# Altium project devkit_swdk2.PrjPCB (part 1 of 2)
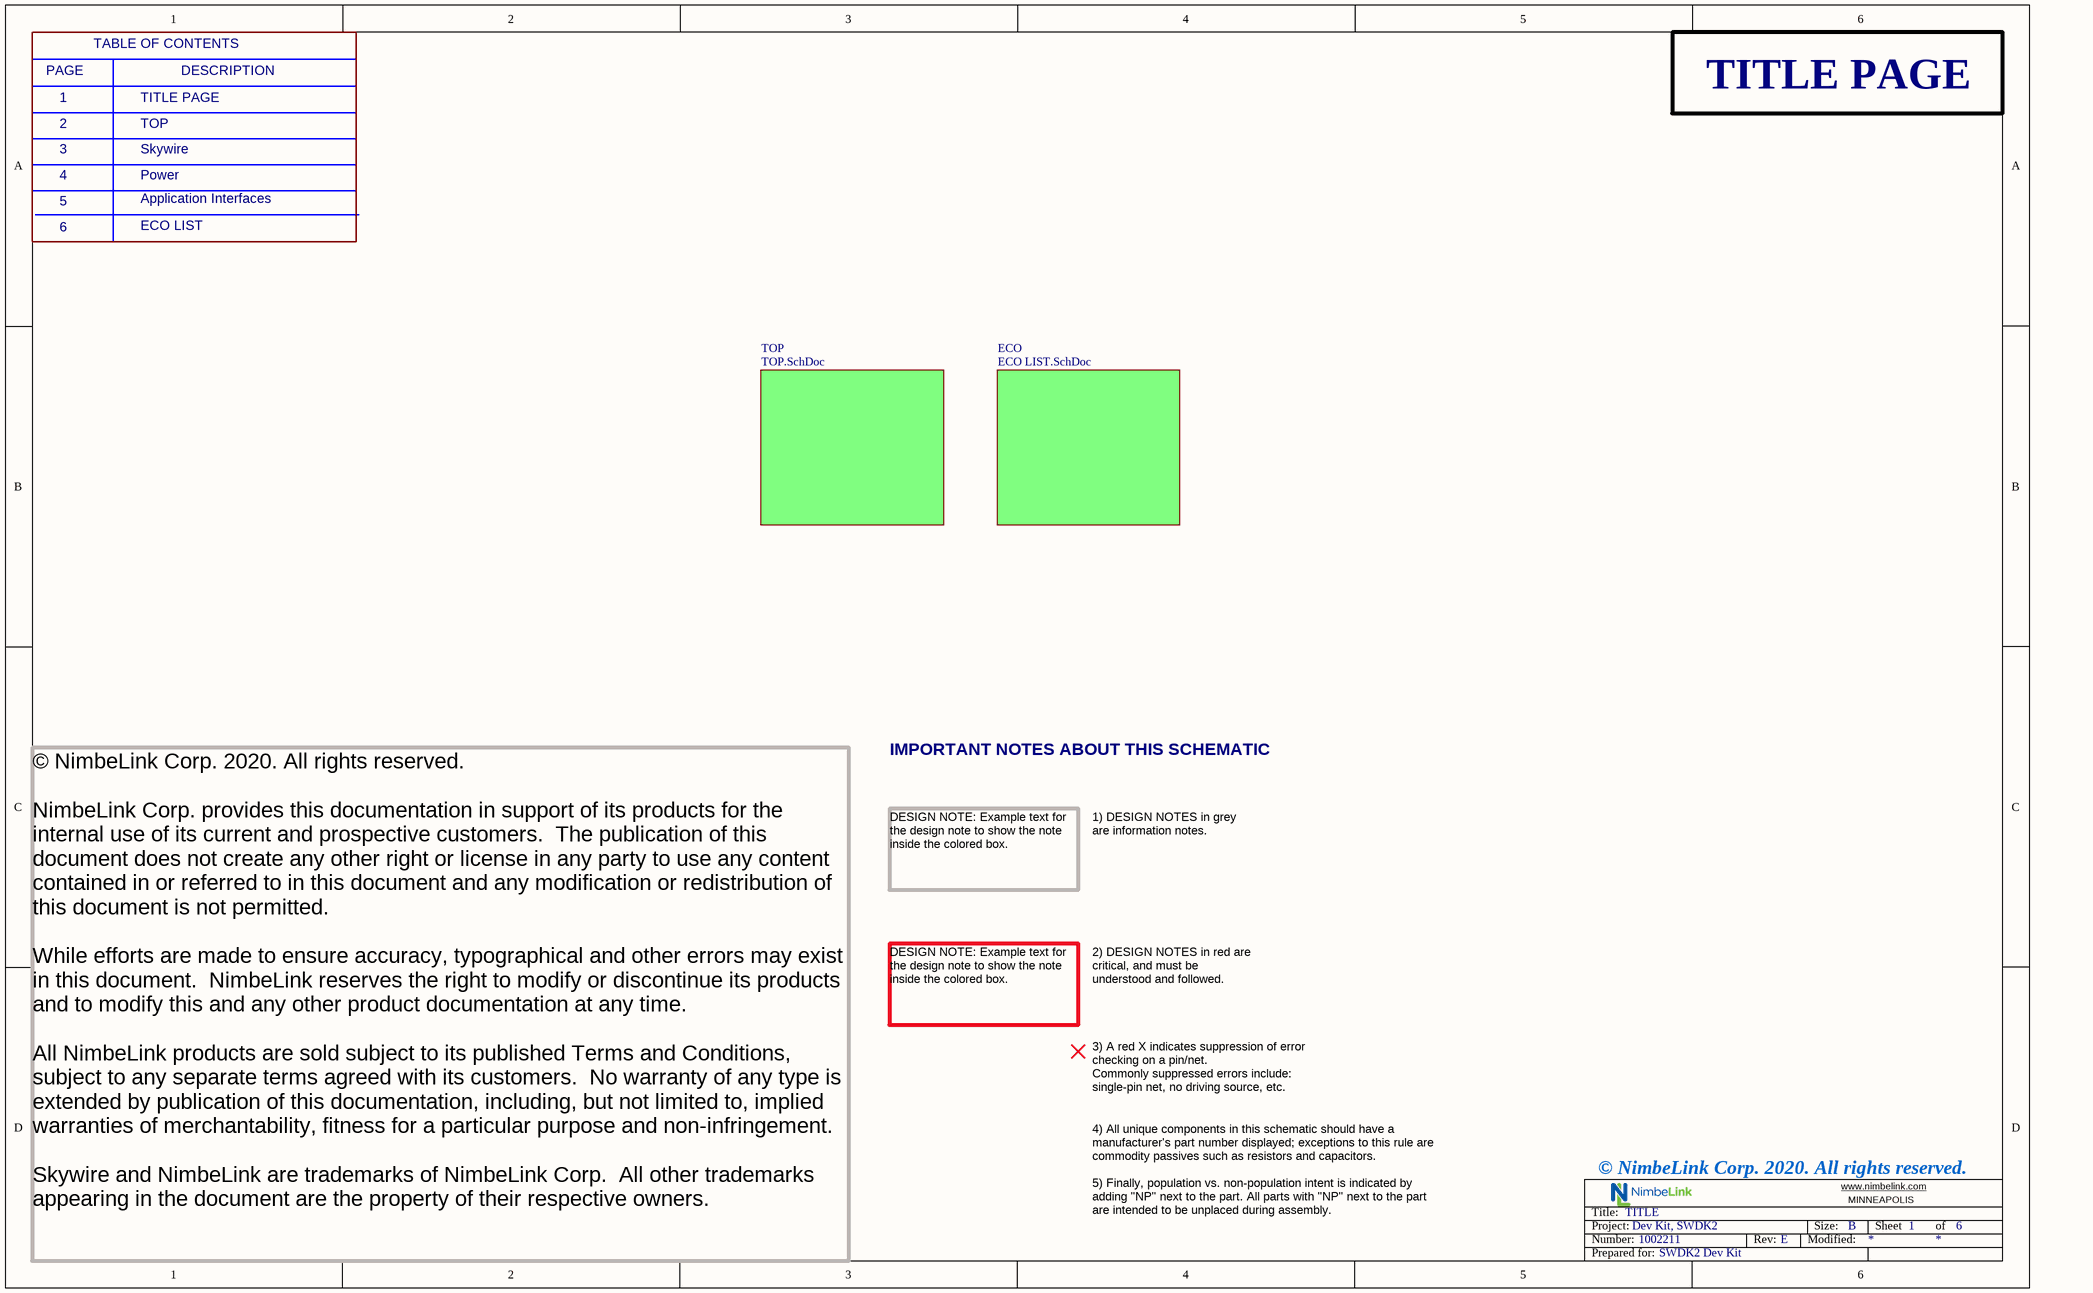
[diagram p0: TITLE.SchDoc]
NL_BILLING_CODE: Dev Kit, SWDK2; NL_PCB_PN: 1003008; NL_PCB_REV: A; NL_PCBA_PN: 1002213; NL_PCBA_REV: J; NL_SCH_PN: 1002211; NL_SCH_REV: E; NL_VERBOSE_CUST_NAME: SWDK2 Dev Kit; ProjectOrganization: Nimbelink, Corp; ProjectTitle: SWDK2 Dev Kit
6 sheets, 225 parts. Net scope: flat (ports and power ports of the same name join across sheets).
Board file: devkit_swdk2.PcbDoc
Sheets:
  TITLE.SchDoc
    TOP = TOP.SchDoc
      Power = Power.SchDoc
      Skywire = Skywire.SchDoc
      Application Interfaces = Application Interfaces.SchDoc
    ECO = ECO LIST.SchDoc

## Sheet TITLE.SchDoc: TITLE
size B; DocumentNumber: 1; SheetNumber: 1; SheetTotal: 6

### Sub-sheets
ECO = ECO LIST.SchDoc: no entries
TOP = TOP.SchDoc: no entries

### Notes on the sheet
- PAGE
- 1
- TABLE OF CONTENTS
- TITLE PAGE
- DESCRIPTION
- 2
- 3
- TOP
- Skywire
- 4
- 5
- 6
- Power
- ECO LIST
- Application Interfaces
- IMPORTANT NOTES ABOUT THIS SCHEMATIC
- DESIGN NOTE: Example text for the design note to show the note inside the colored box.
- 1) DESIGN NOTES in grey are information notes.
- 2) DESIGN NOTES in red are critical, and must be understood and followed.
- 3) A red X indicates suppression of error checking on a pin/net.
  Commonly suppressed errors include: single-pin net, no driving source, etc.
- © NimbeLink Corp. 2020. All rights reserved.
- 4) All unique components in this schematic should have a manufacturer's part number displayed; exceptions to this rule are commodity passives such as resistors and capacitors.
  5) Finally, population vs. non-population intent is indicated by adding "NP" next to the part. All parts with "NP" next to the part are intended to be unplaced during assembly.
- © NimbeLink Corp. 2020. All rights reserved.
  NimbeLink Corp. provides this documentation in support of its products for the internal use of its current and prospective customers.  The publication of this document does not create any other right or license in any party to use any content contained in or referred to in this document and any modification or redistribution of this document is not permitted.
  While efforts are made to ensure accuracy, typographical and other errors may exist in this document.  NimbeLink reserves the right to modify or discontinue its products and to modify this and any other product documentation at any time.
  All NimbeLink products are sold subject to its published Terms and Conditions, subject to any separate terms agreed with its customers.  No warranty of any type is extended by publication of this documentation, including, but not limited to, implied warranties of merchantability, fitness for a particular purpose and non-infringement.
  Skywire and NimbeLink are trademarks of NimbeLink Corp.  All other trademarks appearing in the document are the property of their respective owners.

## Sheet TOP.SchDoc: TOP
size C; DocumentNumber: 2; SheetNumber: 2; SheetTotal: 6
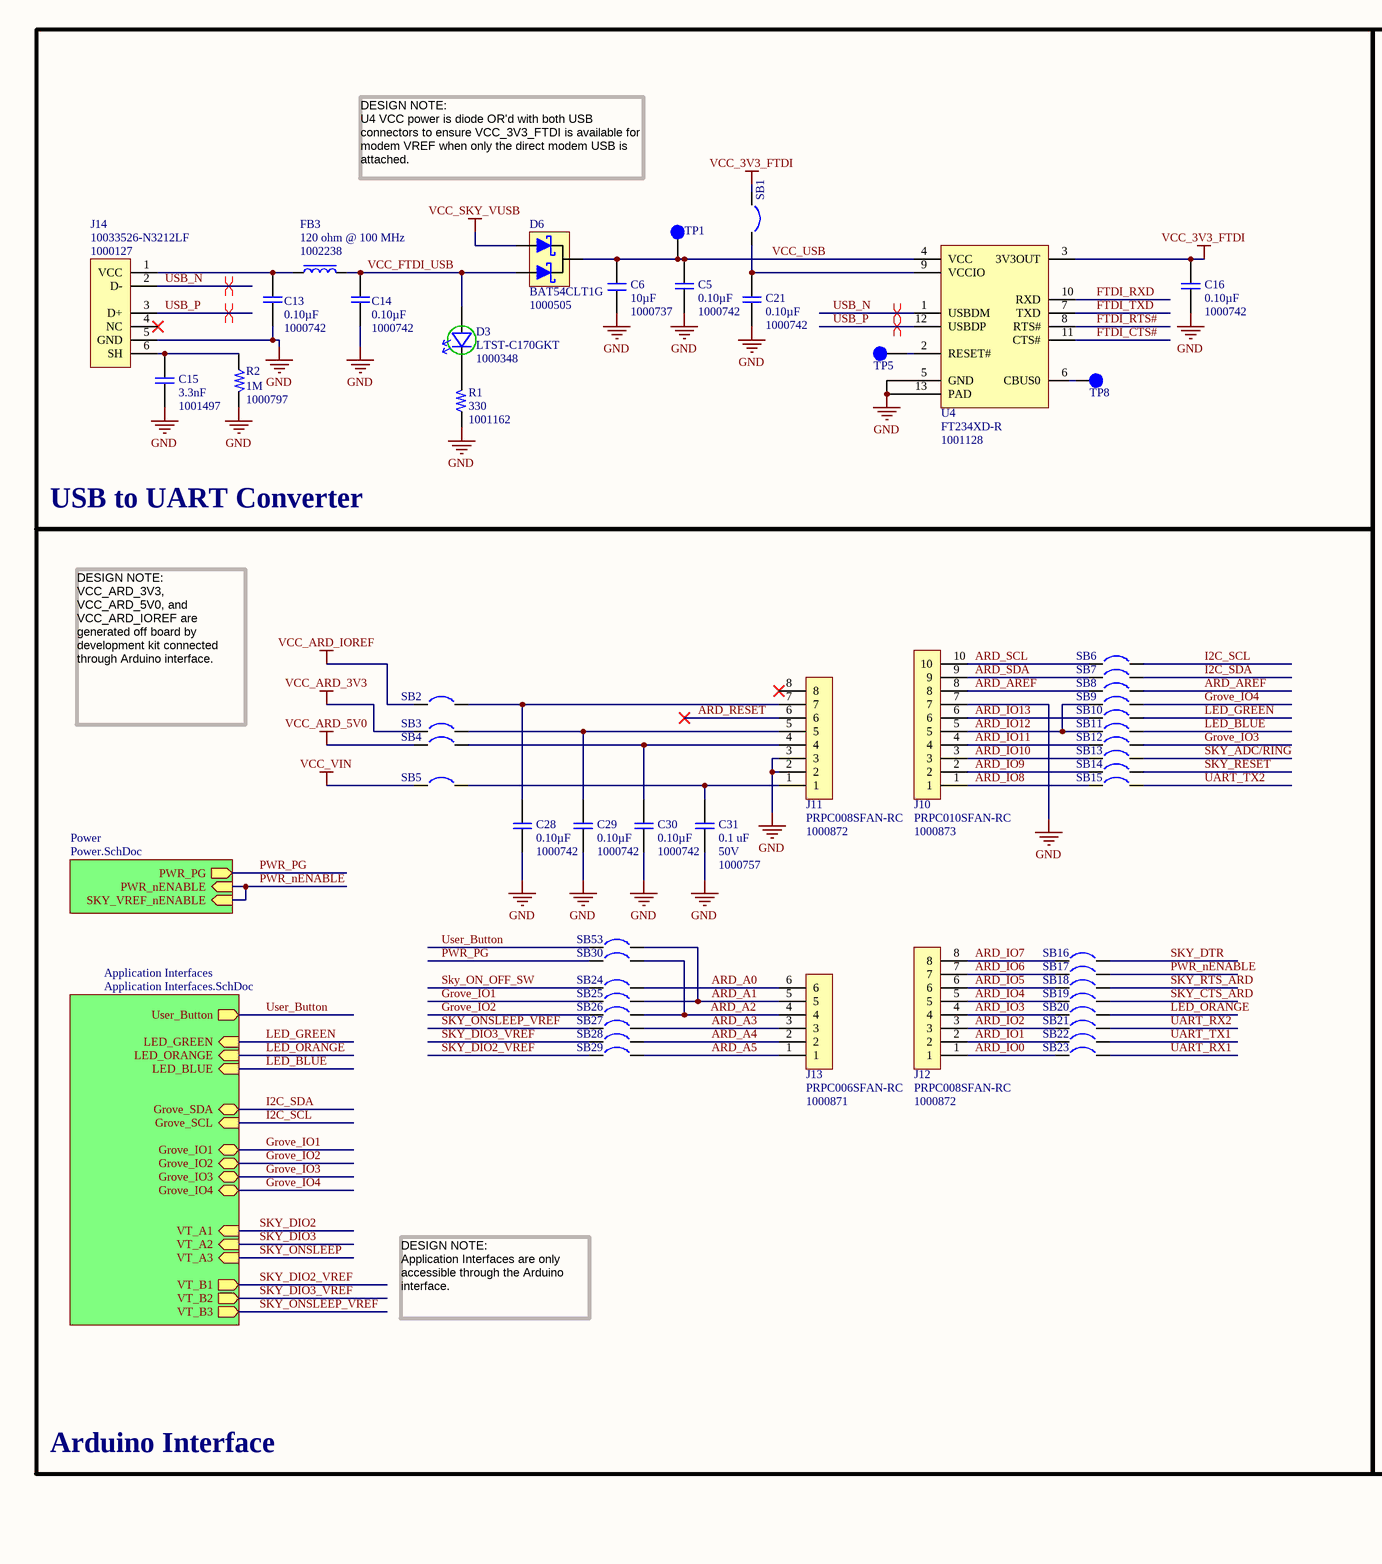
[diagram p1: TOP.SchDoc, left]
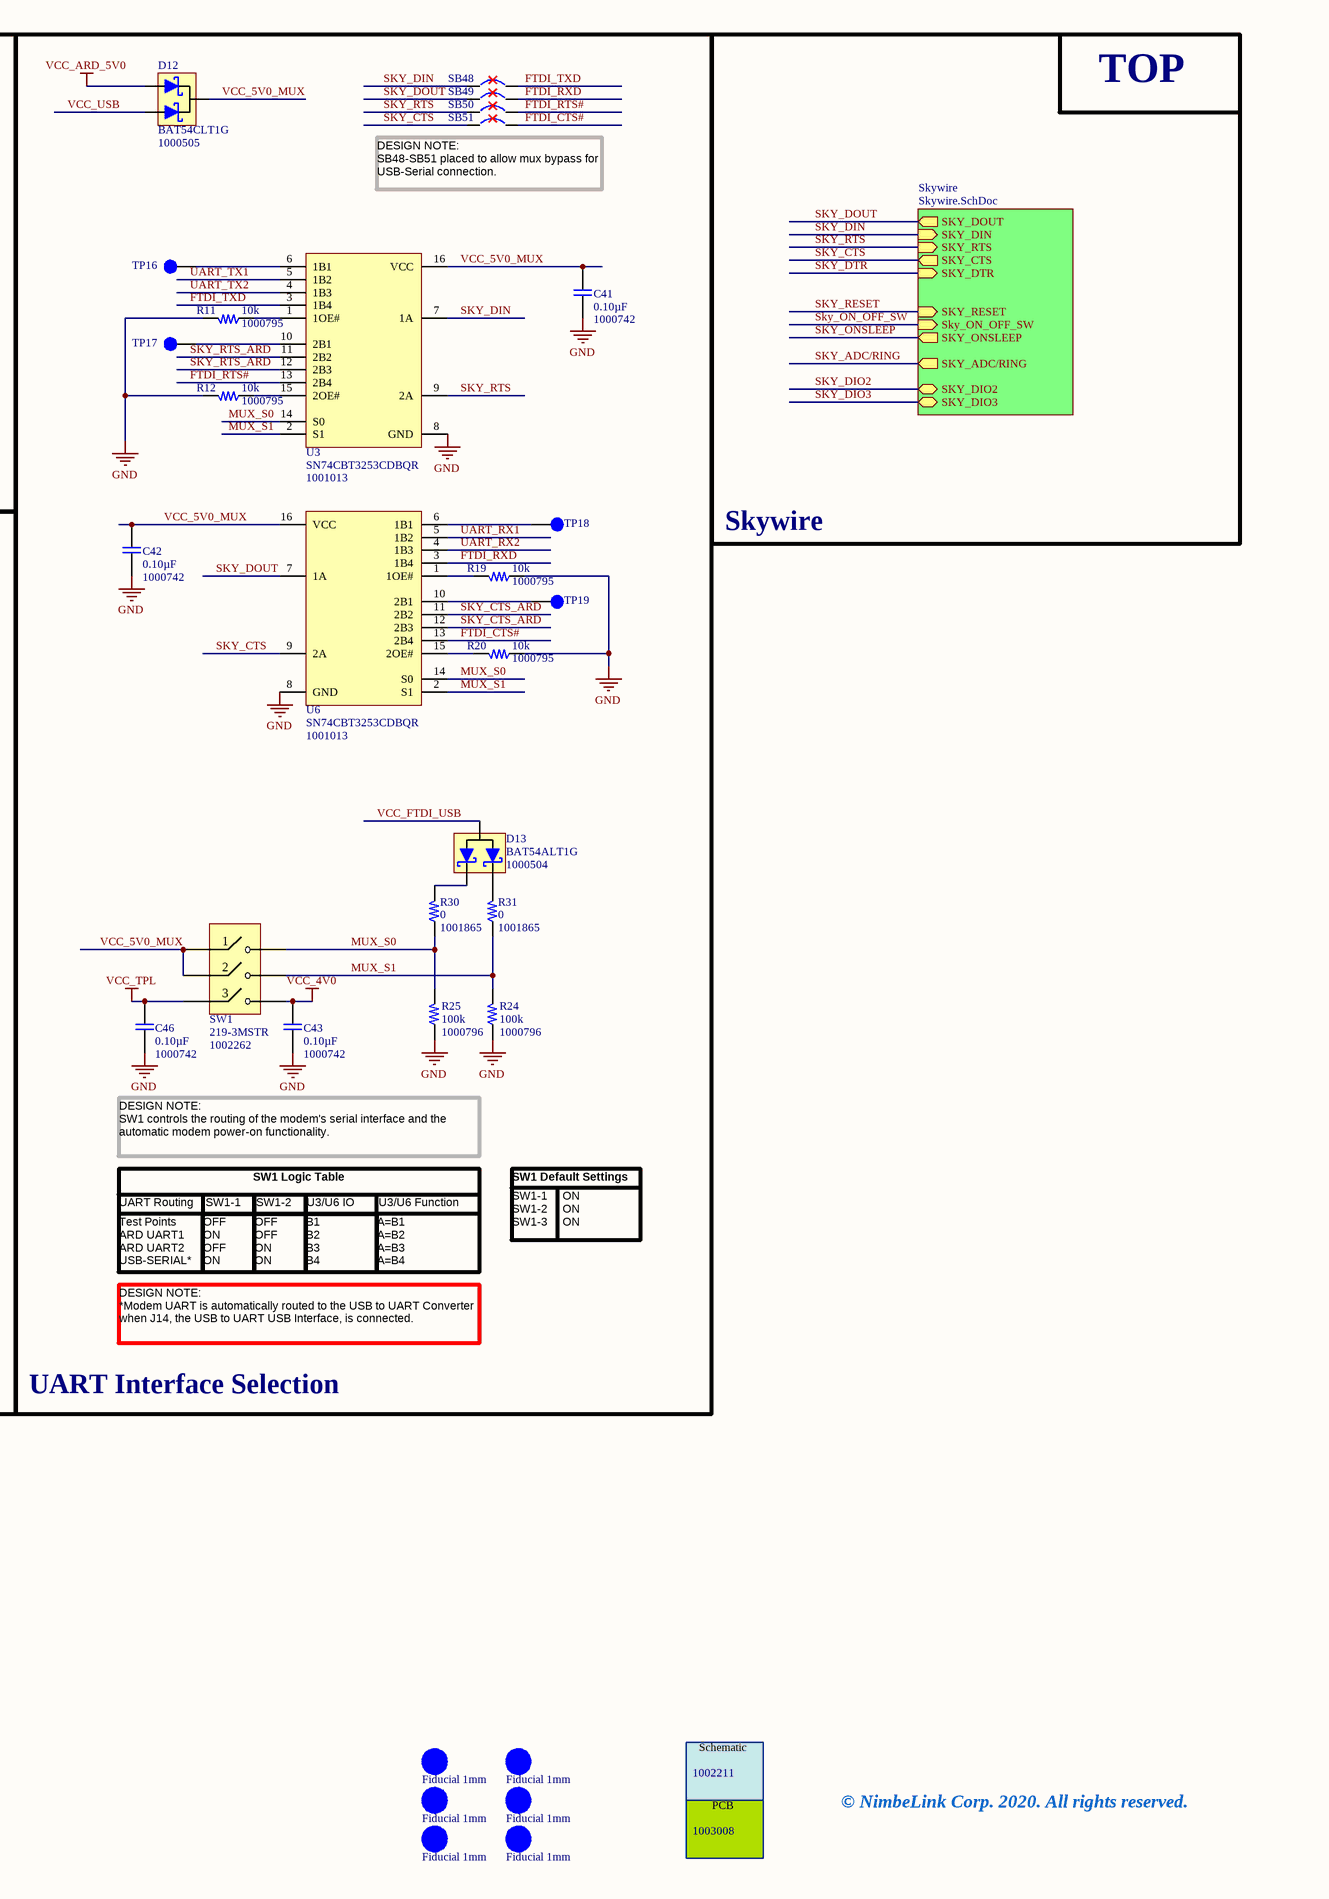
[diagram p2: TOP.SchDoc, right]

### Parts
C5  Capacitance: 0.10µF  Part_Number: 1000742  [0402]
C6  Part_Number: 1000737  Capacitance: 10µF  [0402 +-0.2mm Width]  (hidden comment: C, 10 uF, 10V, X5R, 20%, 0402 CER)
C13  Capacitance: 0.10µF  Part_Number: 1000742  [0402]
C14  Capacitance: 0.10µF  Part_Number: 1000742  [0402]
C15  Part_Number: 1001497  Capacitance: 3.3nF  [0402]  (hidden comment: CAPACITOR)
C16  Capacitance: 0.10µF  Part_Number: 1000742  [0402]
C21  Capacitance: 0.10µF  Part_Number: 1000742  [0402]
C28  Capacitance: 0.10µF  Part_Number: 1000742  [0402]
C29  Capacitance: 0.10µF  Part_Number: 1000742  [0402]
C30  Capacitance: 0.10µF  Part_Number: 1000742  [0402]
C31  Part_Number: 1000757  Capacitance: 0.1 uF  Voltage_Rating: 50V  [0603]  (hidden comment: CAPACITOR)
C41  Capacitance: 0.10µF  Part_Number: 1000742  [0402]
C42  Capacitance: 0.10µF  Part_Number: 1000742  [0402]
C43  Capacitance: 0.10µF  Part_Number: 1000742  [0402]
C46  Capacitance: 0.10µF  Part_Number: 1000742  [0402]
D3  Part_Number: 1000348  [D_LED_GREEN]  (hidden comment: LTST-C170GKT)
D6  Part_Number: 1000505  [SOT23-STYLE9]  (hidden comment: BAT54CLT1G)
D12  Part_Number: 1000505  [SOT23-STYLE9]  (hidden comment: BAT54CLT1G)
D13  Part_Number: 1000504  [SOT23-STYLE9]  (hidden comment: BAT54ALT1G)
FB3  Part_Number: 1002238  Resistance_at_Frequency: 120 ohm @ 100 MHz  [0603]  (hidden comment: FERRITE)
Fiducial1  Fiducial 1mm  [Fiducial 1mm]  (no BOM)
Fiducial2  Fiducial 1mm  [Fiducial 1mm]  (no BOM)
Fiducial3  Fiducial 1mm  [Fiducial 1mm]  (no BOM)
Fiducial4  Fiducial 1mm  [Fiducial 1mm]  (no BOM)
Fiducial5  Fiducial 1mm  [Fiducial 1mm]  (no BOM)
Fiducial6  Fiducial 1mm  [Fiducial 1mm]  (no BOM)
J10  Part_Number: 1000873  [PRPC010SFAN-RC]  (hidden comment: PRPC010SFAN-RC)
J11  Part_Number: 1000872  [PRPC008SFAN-RC]  (hidden comment: PRPC008SFAN-RC)
J12  Part_Number: 1000872  [PRPC008SFAN-RC]  (hidden comment: PRPC008SFAN-RC)
J13  Part_Number: 1000871  [PRPC006SFAN-RC]  (hidden comment: PRPC006SFAN-RC)
J14  Part_Number: 1000127  [10033526-N3212LF]  (hidden comment: USB MINI B)
PCB1  Part_Number: 1003008  (hidden comment: PCB)  (mechanical)
R1  Part_Number: 1001162  Resistance_Ohms: 330  [0402]  (hidden comment: R, 330, 1%, 1/10W, 0402)
R2  Part_Number: 1000797  Resistance_Ohms: 1M  [0402]  (hidden comment: R, 1M, 1%, 1/16W, 0402)
R11  Part_Number: 1000795  Resistance_Ohms: 10k  [0402]  (hidden comment: R, 10K, 1%, 1/16W,  0402)
R12  Part_Number: 1000795  Resistance_Ohms: 10k  [0402]  (hidden comment: R, 10K, 1%, 1/16W,  0402)
R19  Part_Number: 1000795  Resistance_Ohms: 10k  [0402]  (hidden comment: R, 10K, 1%, 1/16W,  0402)
R20  Part_Number: 1000795  Resistance_Ohms: 10k  [0402]  (hidden comment: R, 10K, 1%, 1/16W,  0402)
R24  Part_Number: 1000796  Resistance_Ohms: 100k  [0402]  (hidden comment: R, 100K, 1%, 1/16W,  0402)
R25  Part_Number: 1000796  Resistance_Ohms: 100k  [0402]  (hidden comment: R, 100K, 1%, 1/16W,  0402)
R30  Resistance_Ohms: 0  Part_Number: 1001865  [0402]  (hidden comment: RESISTOR)
R31  Resistance_Ohms: 0  Part_Number: 1001865  [0402]  (hidden comment: RESISTOR)
SB1  Solder Bridge  [Solder Bridge 0603 Closed]  (value not drawn)
SB2  Solder Bridge  [Solder Bridge 0603 Closed]  (value not drawn)
SB3  Solder Bridge  [Solder Bridge 0603 Closed]  (value not drawn)
SB4  Solder Bridge  [Solder Bridge 0603 Closed]  (value not drawn)
SB5  Solder Bridge  [Solder Bridge 0603 Closed]  (value not drawn)
SB6  Solder Bridge  [Solder Bridge 0603 Closed]  (value not drawn)
SB7  Solder Bridge  [Solder Bridge 0603 Closed]  (value not drawn)
SB8  Solder Bridge  [Solder Bridge 0603 Closed]  (value not drawn)
SB9  Solder Bridge  [Solder Bridge 0603 Closed]  (value not drawn)
SB10  Solder Bridge  [Solder Bridge 0603 Closed]  (value not drawn)
SB11  Solder Bridge  [Solder Bridge 0603 Closed]  (value not drawn)
SB12  Solder Bridge  [Solder Bridge 0603 Closed]  (value not drawn)
SB13  Solder Bridge  [Solder Bridge 0603 Closed]  (value not drawn)
SB14  Solder Bridge  [Solder Bridge 0603 Closed]  (value not drawn)
SB15  Solder Bridge  [Solder Bridge 0603 Closed]  (value not drawn)
SB16  Solder Bridge  [Solder Bridge 0603 Closed]  (value not drawn)
SB17  Solder Bridge  [Solder Bridge 0603 Closed]  (value not drawn)
SB18  Solder Bridge  [Solder Bridge 0603 Closed]  (value not drawn)
SB19  Solder Bridge  [Solder Bridge 0603 Closed]  (value not drawn)
SB20  Solder Bridge  [Solder Bridge 0603 Closed]  (value not drawn)
SB21  Solder Bridge  [Solder Bridge 0603 Closed]  (value not drawn)
SB22  Solder Bridge  [Solder Bridge 0603 Closed]  (value not drawn)
SB23  Solder Bridge  [Solder Bridge 0603 Closed]  (value not drawn)
SB24  Solder Bridge  [Solder Bridge 0603 Closed]  (value not drawn)
SB25  Solder Bridge  [Solder Bridge 0603 Closed]  (value not drawn)
SB26  Solder Bridge  [Solder Bridge 0603 Closed]  (value not drawn)
SB27  Solder Bridge  [Solder Bridge 0603 Closed]  (value not drawn)
SB28  Solder Bridge  [Solder Bridge 0603 Closed]  (value not drawn)
SB29  Solder Bridge  [Solder Bridge 0603 Closed]  (value not drawn)
SB30  Solder Bridge  [Solder Bridge 0603 Closed]  (value not drawn)
SB48  Solder Bridge  [SOLDER BRIDGE 0603]  (value not drawn)  (no BOM)
SB49  Solder Bridge  [SOLDER BRIDGE 0603]  (value not drawn)  (no BOM)
SB50  Solder Bridge  [SOLDER BRIDGE 0603]  (value not drawn)  (no BOM)
SB51  Solder Bridge  [SOLDER BRIDGE 0603]  (value not drawn)  (no BOM)
SB53  Solder Bridge  [Solder Bridge 0603 Closed]  (value not drawn)
SCH1  Part_Number: 1002211  (hidden comment: SCH)  (mechanical)
SW1  Part_Number: 1002262  [219-3MSTR]  (hidden comment: DIP-3pin)
TP1  Test Point 1mm  [Test_Point 1mm]  (value not drawn)  (no BOM)
TP5  Test Point 1mm  [Test_Point 1mm]  (value not drawn)  (no BOM)
TP8  Test Point 1mm  [Test_Point 1mm]  (value not drawn)  (no BOM)
TP16  Test Point 1mm  [Test_Point 1mm]  (value not drawn)  (no BOM)
TP17  Test Point 1mm  [Test_Point 1mm]  (value not drawn)  (no BOM)
TP18  Test Point 1mm  [Test_Point 1mm]  (value not drawn)  (no BOM)
TP19  Test Point 1mm  [Test_Point 1mm]  (value not drawn)  (no BOM)
U3  Part_Number: 1001013  [SN74CBT3253CDBQR]  (hidden comment: SN74CBT3253CDBQR)
U4  Manufacturer_Part_Number1: FT234XD-R  Part_Number: 1001128  [QFN45P300X300X80_HS-13N]  (hidden comment: FT234XD)
U6  Part_Number: 1001013  [SN74CBT3253CDBQR]  (hidden comment: SN74CBT3253CDBQR)

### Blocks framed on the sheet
USB to UART Converter: C5 C6 C13-C16 C21 D3 D6 FB3 J14 R1 R2 SB1 TP1 TP5 TP8 U4
UART Interface Selection: C41-C43 C46 D12 D13 R11 R12 R19 R20 R24 R25 R30 R31 SB48-SB51 SW1 TP16-TP19 U3 U6
Arduino Interface: C28-C31 J10-J13 SB2-SB30 SB53

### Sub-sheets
Application Interfaces = Application Interfaces.SchDoc: Grove_IO1 (bidir), Grove_SDA (bidir), User_Button (out), Grove_IO4 (bidir), Grove_IO2 (bidir), LED_GREEN (in), LED_ORANGE (in), Grove_IO3 (bidir), LED_BLUE (in), Grove_SCL (in), VT_A1 (in), VT_A2 (in), VT_A3 (in), VT_B1 (out), VT_B2 (out), VT_B3 (out)
Power = Power.SchDoc: PWR_PG (out), PWR_nENABLE (in), SKY_VREF_nENABLE (in)
Skywire = Skywire.SchDoc: SKY_RESET (in), SKY_CTS (out), SKY_DOUT (out), SKY_DIN (in), Sky_ON_OFF_SW (in), SKY_RTS (in), SKY_DTR (in), SKY_ONSLEEP (out), SKY_DIO2 (bidir), SKY_DIO3 (bidir), SKY_ADC/RING (out)

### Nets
GND: C5.2 C6.2 C13.2 C14.2 C15.1 C16.2 C21.2 C28.2 C29.2 C30.2 C31.2 C41.2 C42.2 C43.2 C46.2 J10.7 J11.2 J11.3 J14.5(GND) R1.1 R2.1 R11.2 R12.2 R19.1 R20.1 R24.1 R25.1 U3.8(GND) U4.5(GND) U4.13(PAD) U6.8(GND)
VCC_3V3_FTDI: C16.1 SB1.1 U4.3(3V3OUT)
VCC_4V0: C43.1 SW1.4
VCC_ARD_3V3: SB3.1
VCC_ARD_5V0: D12.2 SB4.1
VCC_ARD_IOREF: SB2.1
VCC_SKY_VUSB: D6.2
VCC_TPL: C46.1 SW1.3
VCC_VIN: SB5.1
ARD_A0: J13.6 SB24.2
ARD_A1: J13.5 SB25.2 SB53.2
ARD_A2: J13.4 SB26.2 SB30.2
ARD_A3: J13.3 SB27.2
ARD_A4: J13.2 SB28.2
ARD_A5: J13.1 SB29.2
ARD_AREF: J10.8 SB8.1 SB8.2
ARD_IO0: J12.1 SB23.1
ARD_IO1: J12.2 SB22.1
ARD_IO2: J12.3 SB21.1
ARD_IO3: J12.4 SB20.1
ARD_IO4: J12.5 SB19.1
ARD_IO5: J12.6 SB18.1
ARD_IO6: J12.7 SB17.1
ARD_IO7: J12.8 SB16.1
ARD_IO8: J10.1 SB15.1
ARD_IO9: J10.2 SB14.1
ARD_IO10: J10.3 SB13.1
ARD_IO11: J10.4 SB12.1
ARD_IO12: J10.5 SB9.1 SB11.1
ARD_IO13: J10.6 SB10.1
ARD_RESET: J11.6
ARD_SCL: J10.10 SB6.1
ARD_SDA: J10.9 SB7.1
FTDI_CTS#: SB51.2 U4.11(CTS#) U6.13(2B4)
FTDI_RTS#: SB50.2 U3.13(2B4) U4.8(RTS#)
FTDI_RXD: SB49.2 U4.10(RXD) U6.3(1B4)
FTDI_TXD: SB48.2 U3.3(1B4) U4.7(TXD)
Grove_IO1: SB25.1 ; sheet Application Interfaces/Grove_IO1
Grove_IO2: SB26.1 ; sheet Application Interfaces/Grove_IO2
Grove_IO3: SB12.2 ; sheet Application Interfaces/Grove_IO3
Grove_IO4: SB9.2 ; sheet Application Interfaces/Grove_IO4
I2C_SCL: SB6.2 ; sheet Application Interfaces/Grove_SCL
I2C_SDA: SB7.2 ; sheet Application Interfaces/Grove_SDA
LED_BLUE: SB11.2 ; sheet Application Interfaces/LED_BLUE
LED_GREEN: SB10.2 ; sheet Application Interfaces/LED_GREEN
LED_ORANGE: SB20.2 ; sheet Application Interfaces/LED_ORANGE
MUX_S0: R25.2 R30.1 SW1.6 U3.14(S0) U6.14(S0)
MUX_S1: R24.2 R31.1 SW1.5 U3.2(S1) U6.2(S1)
PWR_nENABLE: SB17.2 ; sheet Power/PWR_nENABLE, sheet Power/SKY_VREF_nENABLE
PWR_PG: SB30.1 ; sheet Power/PWR_PG
SKY_ADC/RING: SB13.2 ; sheet Skywire/SKY_ADC/RING
SKY_CTS: SB51.1 U6.9(2A) ; sheet Skywire/SKY_CTS
SKY_CTS_ARD: SB19.2 U6.11(2B2) U6.12(2B3)
SKY_DIN: SB48.1 U3.7(1A) ; sheet Skywire/SKY_DIN
SKY_DIO2: sheet Skywire/SKY_DIO2, sheet Application Interfaces/VT_A1
SKY_DIO2_VREF: SB29.1 ; sheet Application Interfaces/VT_B1
SKY_DIO3: sheet Skywire/SKY_DIO3, sheet Application Interfaces/VT_A2
SKY_DIO3_VREF: SB28.1 ; sheet Application Interfaces/VT_B2
SKY_DOUT: SB49.1 U6.7(1A) ; sheet Skywire/SKY_DOUT
SKY_DTR: SB16.2 ; sheet Skywire/SKY_DTR
Sky_ON_OFF_SW: SB24.1 ; sheet Skywire/Sky_ON_OFF_SW
SKY_ONSLEEP: sheet Skywire/SKY_ONSLEEP, sheet Application Interfaces/VT_A3
SKY_ONSLEEP_VREF: SB27.1 ; sheet Application Interfaces/VT_B3
SKY_RESET: SB14.2 ; sheet Skywire/SKY_RESET
SKY_RTS: SB50.1 U3.9(2A) ; sheet Skywire/SKY_RTS
SKY_RTS_ARD: SB18.2 U3.11(2B2) U3.12(2B3)
UART_RX1: SB23.2 U6.5(1B2)
UART_RX2: SB21.2 U6.4(1B3)
UART_TX1: SB22.2 U3.5(1B2)
UART_TX2: SB15.2 U3.4(1B3)
USB_N: J14.2(D-) U4.1(USBDM)
USB_P: J14.3(D+) U4.12(USBDP)
User_Button: SB53.1 ; sheet Application Interfaces/User_Button
VCC_5V0_MUX: C41.1 C42.1 D12.3 SW1.1 SW1.2 U3.16(VCC) U6.16(VCC)
VCC_FTDI_USB: C14.1 D3.1(Anode) D6.1 D13.3 FB3.2
VCC_USB: C5.1 C6.1 D6.3 D12.1 TP1.1 U4.4(VCC)
NetC13_1: C13.1 FB3.1 J14.1(VCC)
NetC15_2: C15.2 J14.6(SH) R2.2
NetC21_1: C21.1 SB1.2 U4.9(VCCIO)
NetC28_1: C28.1 J11.7 SB2.2
NetC29_1: C29.1 J11.5 SB3.2
NetC30_1: C30.1 J11.4 SB4.2
NetC31_1: C31.1 J11.1 SB5.2
NetD3_2: D3.2(Cathode) R1.2
NetD13_1: D13.1 R30.2
NetD13_2: D13.2 R31.2
NetR11_1: R11.1 U3.1(1OE#)
NetR12_1: R12.1 U3.15(2OE#)
NetR19_2: R19.2 U6.1(1OE#)
NetR20_2: R20.2 U6.15(2OE#)
NetTP5_1: TP5.1 U4.2(RESET#)
NetTP8_1: TP8.1 U4.6(CBUS0)
NetTP16_1: TP16.1 U3.6(1B1)
NetTP17_1: TP17.1 U3.10(2B1)
NetTP18_1: TP18.1 U6.6(1B1)
NetTP19_1: TP19.1 U6.10(2B1)

Not connected (* = marked no-connect by the designer): J11 8*; J14 4(NC)*

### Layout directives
differential pair: USB_N, USB_P

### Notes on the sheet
- TOP
- DESIGN NOTE:
  U4 VCC power is diode OR'd with both USB connectors to ensure VCC_3V3_FTDI is available for modem VREF when only the direct modem USB is attached.
- (near SB51) DESIGN NOTE:
  SB48-SB51 placed to allow mux bypass for USB-Serial connection.
- Skywire
- DESIGN NOTE:
  VCC_ARD_3V3, VCC_ARD_5V0, and VCC_ARD_IOREF are generated off board by development kit connected through Arduino interface.
- DESIGN NOTE:
  SW1 controls the routing of the modem's serial interface and the automatic modem power-on functionality.
- SW1 Default Settings
- SW1 Logic Table
- SW1-1     ON
  SW1-2     ON
  SW1-3     ON
- DESIGN NOTE:
  Application Interfaces are only accessible through the Arduino interface.
- UART Routing    SW1-1     SW1-2     U3/U6 IO        U3/U6 Function
- Test Points
  ARD UART1
  ARD UART2
  USB-SERIAL*
- OFF
  ON
  OFF
  ON
- OFF
  OFF
  ON
  ON
- B1
  B2
  B3
  B4
- A=B1
  A=B2
  A=B3
  A=B4
- DESIGN NOTE:
  *Modem UART is automatically routed to the USB to UART Converter when J14, the USB to UART USB Interface, is connected.
- © NimbeLink Corp. 2020. All rights reserved.

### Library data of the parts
C5 C13 C14 C16 C21 C28-C30 C41-C43 C46 = 1000742: Capacitor, 0.1 uF, 16V, 10%, X7R, 0402; Manufacturer1: Kemet; Manufacturer_Part_Number1: C0402C104K4RALTU; Item_Phase: Production; Capacitor_Type: Ceramic; Mounting_Type: Surface Mount; Operating_Temperature: -55°C ~ 125°C; Thickness_Max: 0.022" (0.55mm)
C6 = 1000737: Capacitor, 10 uF, 10V, 20%, X5R, 0402; Manufacturer1: Venkel LTD.; Manufacturer_Part_Number1: C0402X5R100-106MNP; Item_Phase: Production; Capacitor_Type: Ceramic; Mounting_Type: Surface Mount; Operating_Temperature: -55°C ~ 85°C; Thickness_Max: 0.035" (0.90mm)
C15 = 1001497: Capacitor, 3.3 nF, 50V, 10%, X7R, 0402; Manufacturer1: Murata; Manufacturer_Part_Number1: GRM155R71H332KA01D; Item_Phase: Production; Capacitor_Type: Ceramic; Mounting_Type: Surface Mount; Operating_Temperature: -55°C ~ 125°C; Thickness_Max: 0.022" (0.55mm)
C31 = 1000757: Capacitor, 0.1 uF, 50V, 10%, X7R, 0603; Manufacturer1: TDK Corporation; Manufacturer_Part_Number1: CGA3E2X7R1H104K080AA; Item_Phase: Production; Capacitor_Type: Ceramic; Mounting_Type: Surface Mount; Operating_Temperature: -55 to 125C
D3 = 1000348: Diode, LED, Green, 6mcd, 569nm, 0805; Manufacturer1: Lite-On Inc; Item_Phase: Production
D6 D12 = 1000505: Diode, Schottky, Dual, COM CATHODE, 30V, 0.35VF, 200MA, SOT23; Manufacturer1: ON Semiconductor; Item_Phase: Production; Current_Average_Rectified_IO: 200mA (DC); Current_Reverse_Leakage_at_Vref: 2µA @ 25V; Mounting_Type: Surface Mount; Voltage_Forward_VF_Max_at_I_Forward: 800mV @ 100mA
D13 = 1000504: Diode, Schottky, Dual, COM ANODE, 30V, 0.35 Vf, 200MA, SOT23; Manufacturer1: ON Semiconductor; Item_Phase: Production; Current_Average_Rectified_IO: 200mA (DC); Current_Reverse_Leakage_at_Vref: 2µA @ 25V; Mounting_Type: Surface Mount; Voltage_Forward_VF_Max_at_I_Forward: 800mV @ 100mA
FB3 = 1002238: Ferrite Bead, 120 ohm @100MHz, 3A, 30mOHM-DC, 0603; Manufacturer_Part_Number1: CIS10P121AC; Manufacturer1: Samsung Electro-Mechanics America, Inc; Item_Phase: Production; Mounting_Type: Surface Mount; Operating_Temperature: -55°C ~ 125°C; Resistance_DC: 30 mOhm
Fiducial1-Fiducial6 = Fiducial: Population: NP
J10 = 1000873: Connector, Header, Male, 2.54mm, 10x1, TH 8.08mm; Manufacturer1: Sullins Connector Solutions; Item_Phase: Production; Connector_Type: Header, Unshrouded, Breakaway; Contact_Finish: Gold; Contact_Type: Male Pin; Mounting_Type: Through Hole; Number_of_Positions: 10; Number_of_Positions_Loaded: All; Number_of_Rows: 1; Pitch: 0.100" (2.54mm)
J11 J12 = 1000872: Connector, Header, Male, 2.54mm, 8x1, TH, 8.08mm; Manufacturer1: Sullins Connector Solutions; Item_Phase: Production; Connector_Type: Header, Unshrouded, Breakaway; Contact_Finish: Gold; Contact_Type: Male Pin; Mounting_Type: Through Hole; Number_of_Positions: 8; Number_of_Positions_Loaded: All; Number_of_Rows: 1; Pitch: 0.100" (2.54mm)
J13 = 1000871: Connector, Header, Male, 2.54mm, 6x1, TH, 8.08mm; Manufacturer1: Sullins Connector Solutions; Item_Phase: Production; Connector_Type: Header, Unshrouded, Breakaway; Contact_Finish: Gold; Contact_Type: Male Pin; Mounting_Type: Through Hole; Number_of_Positions: 6; Number_of_Positions_Loaded: All; Number_of_Rows: 1; Pitch: 0.100" (2.54mm)
J14 = 1000127: Connector, USB, Mini B, Right Angle, SMD; Manufacturer1: Amphenol; Gender: Receptacle; Item_Phase: Production; Connector_Type: USB - mini B; Mounting_Type: Surface Mount Right Angle Horizontal; Number_of_Pins: 5
PCB1 = PCB: PCB Part Number
R1 = 1001162: Resistor, 330, 1%, 1/10W, 0402; Manufacturer1: Panasonic Electronic Components; Manufacturer_Part_Number1: ERJ-2RKF3300X; Item_Phase: Production; Mounting_Type: Surface Mount; Number_of_Terminations: 2; Operating_Temperature: -55°C ~ 155°C; Power: 0.1W, 1/10W; Resistor_Package: 0402 (1005 Metric); Temperature_Coefficient: ±100ppm/°C
R2 = 1000797: Resistor, 1M, 1%, 1/16W, 0402; Manufacturer1: Samsung Electro-Mechanics America, Inc; Manufacturer_Part_Number1: RC1005F105CS; Item_Phase: Production; Mounting_Type: Surface Mount; Number_of_Terminations: 2; Operating_Temperature: -55°C ~ 155°C; Power: 0.063W, 1/16W; Resistor_Package: 0402 (1005 Metric); Temperature_Coefficient: ±100ppm/°C
R11 R12 R19 R20 = 1000795: Resistor, 10K, 1%, 1/16W, 0402; Manufacturer1: Bourns Inc; Manufacturer_Part_Number1: CR0402-FX-1002GLF; Item_Phase: Production; Mounting_Type: Surface Mount; Number_of_Terminations: 2; Operating_Temperature: -55°C ~ 155°C; Power: 0.063W, 1/16W; Resistor_Package: 0402 (1005 Metric); Temperature_Coefficient: ±100ppm/°C
R24 R25 = 1000796: Resistor, 100K, 1%, 1/16W, 0402; Manufacturer1: Bourns Inc; Manufacturer_Part_Number1: CR0402-FX-1003GLF; Item_Phase: Production; Mounting_Type: Surface Mount; Number_of_Terminations: 2; Operating_Temperature: -55°C ~ 155°C; Power: 0.063W, 1/16W; Resistor_Package: 0402 (1005 Metric); Temperature_Coefficient: ±100ppm/°C
R30 R31 = 1001865: Resistor, 0, 1/16W, 0402; Manufacturer1: Bourns Inc; Manufacturer_Part_Number1: CR0402-J/-000GLF; Item_Phase: Production; Mounting_Type: Surface Mount; Number_of_Terminations: 2; Operating_Temperature: -55C ~ 155C; Resistor_Package: 0402 (1005 Metric)
SB1-SB30 SB53 = 1002269: Resistor, Solder Bridge, 0, 1/10W, 0603; Manufacturer_Part_Number1: ERJ-3GEY0R00V; Manufacturer1: Panasonic Electronic Components; Resistance_Ohms: 0; Item_Phase: Production; Mounting_Type: Surface Mount; Operating_Temperature: -55°C ~ 155°C; Resistor_Package: 0603 (1608 Metric)
SB48-SB51 = Solder Bridge, Open: Population: NP
SCH1 = SCH: Schematic Part Number
SW1 = 1002262: Switch, SPST, DIP 3, 20V, 0.1A, Washable, Raised Actuator, SMD; Manufacturer1: CTS; Item_Phase: Production; Actuator_Type: Slide; Mounting_Type: Surface Mount; Operating_Temperature: -55°C ~ 85°C
TP1 TP5 TP8 TP16-TP19 = TP_1mm: TEST POINT, SMD 1mm; Population: NP
U3 U6 = 1001013: IC, Multiplexer, Dual, 4:1, 4.5V-5.5V, SSOP-16; Manufacturer1: Texas Instruments; Item_Phase: Production; Mounting_Type: Surface Mount
U4 = 1001128: IC, Interface, UART-USB, 5V, DFN, 3x3mm; Manufacturer1: FTDI, Future Technology Devices International Ltd; Item_Phase: Production; Current_Supply: 8mA; Operating_Temperature: -40°C ~ 85°C; Voltage_Supply_Max: 5.5V; Voltage_Supply_Min: 2.97V

## Sheet Power.SchDoc: POWER
size B; DocumentNumber: 4; SheetNumber: 4; SheetTotal: 6
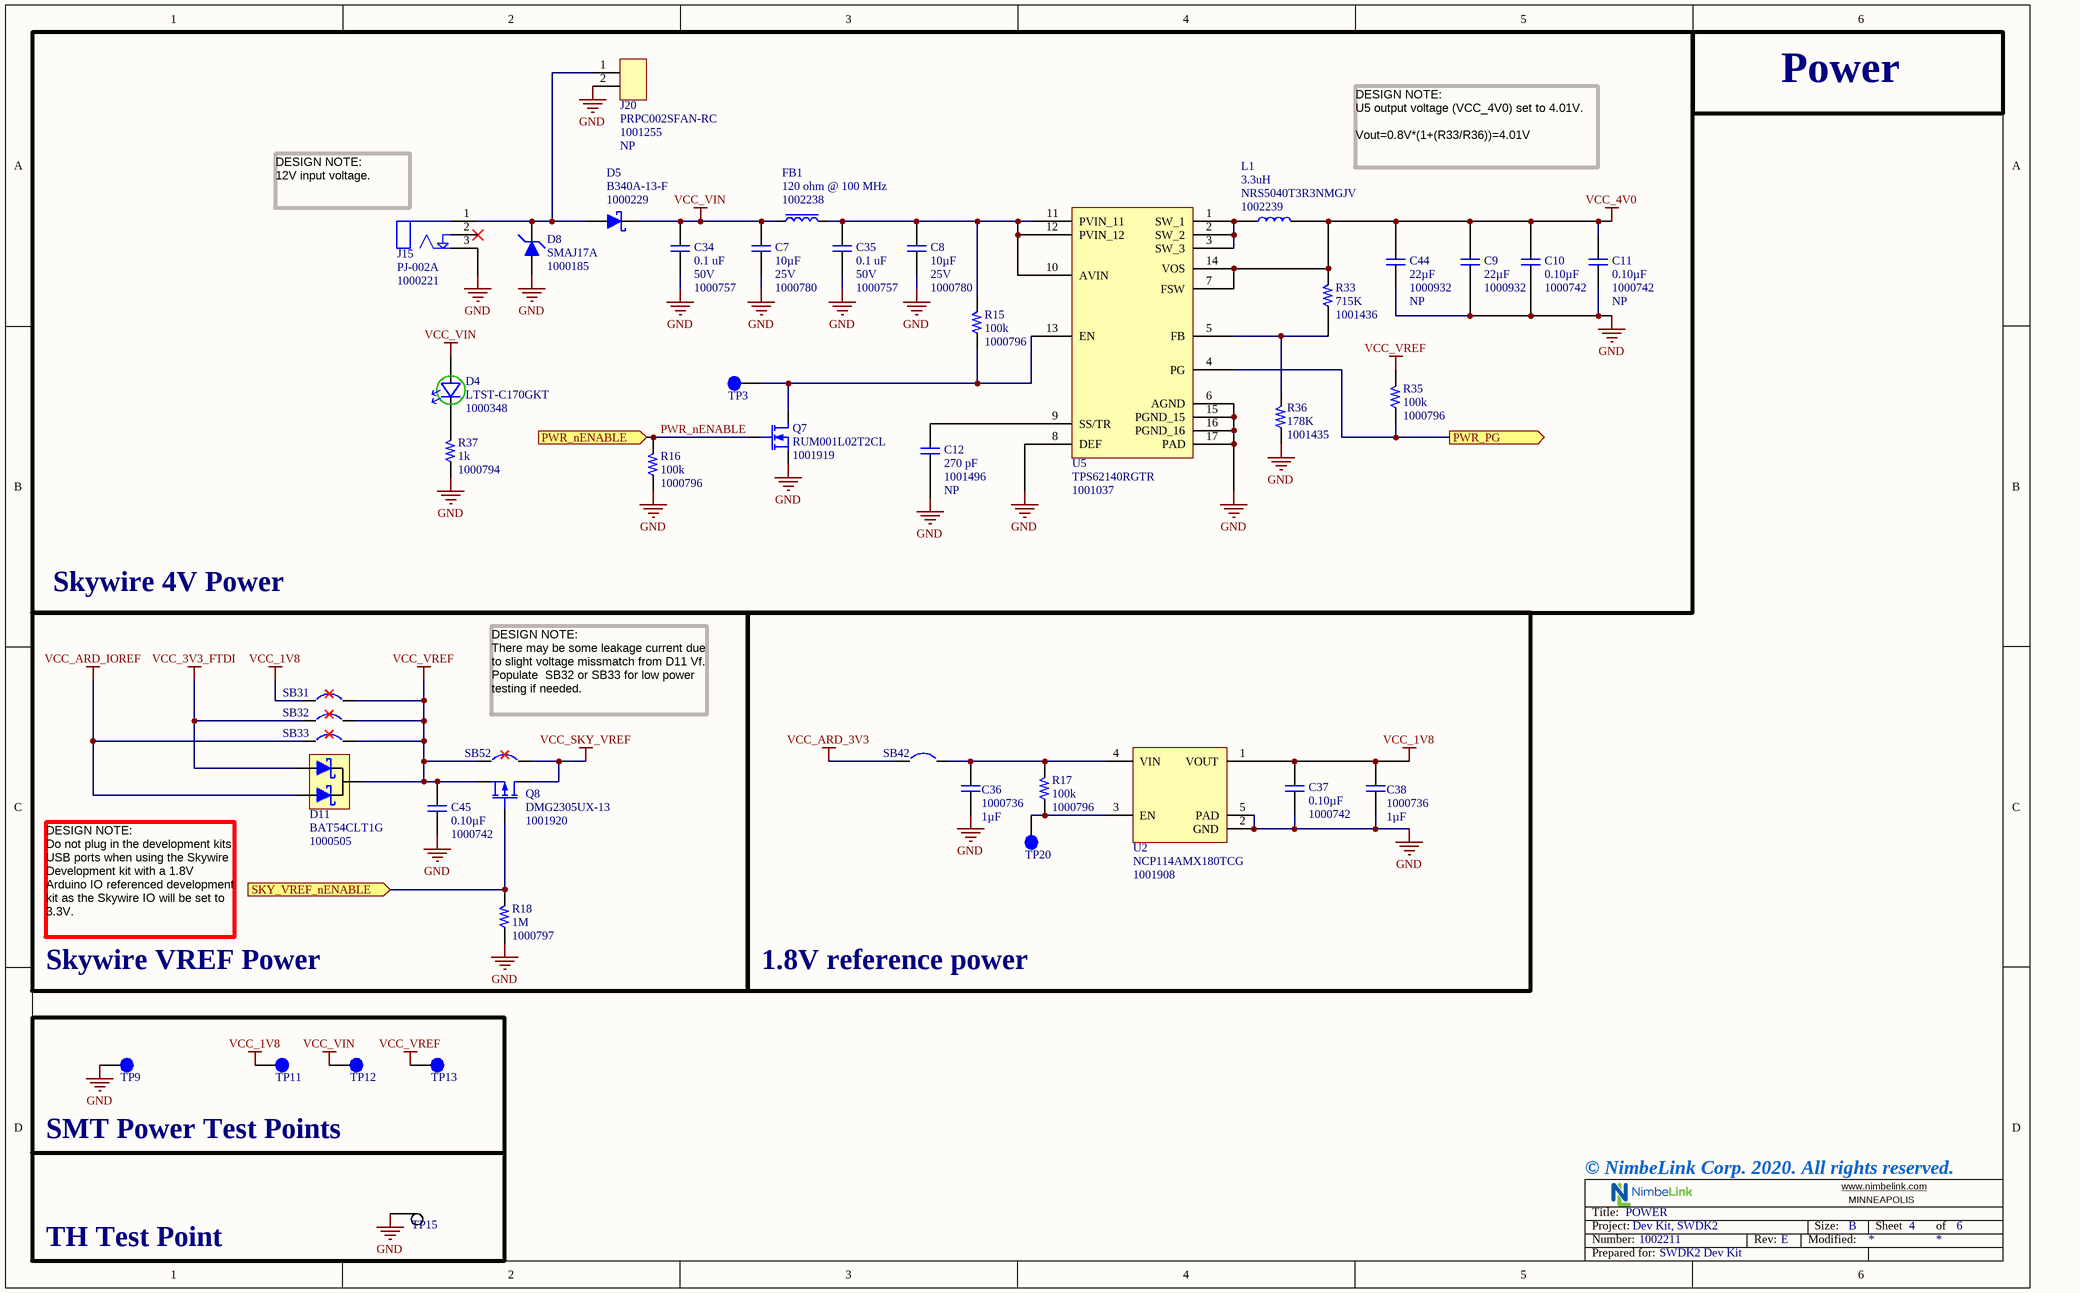
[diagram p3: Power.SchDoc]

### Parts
C7  Part_Number: 1000780  Capacitance: 10µF  Voltage_Rating: 25V  [0805]  (hidden comment: C, 10 uF, 25V, 10% ,X5R, 0805 CER)
C8  Part_Number: 1000780  Capacitance: 10µF  Voltage_Rating: 25V  [0805]  (hidden comment: C, 10 uF, 25V, 10% ,X5R, 0805 CER)
C9  Capacitance: 22µF  [0603]  (hidden comment: 1000932)
C10  Part_Number: 1000742  Capacitance: 0.10µF  [0402]  (hidden comment: C, 0.1 uF, 16V, 10%, X7R, 0402 CER)
C11  Population: NP  Part_Number: 1000742  Capacitance: 0.10µF  [0402]  (hidden comment: C, 0.1 uF, 16V, 10%, X7R, 0402 CER)
C12  Population: NP  Part_Number: 1001496  Capacitance: 270 pF  [0402]  (hidden comment: CAPACITOR)
C34  Part_Number: 1000757  Capacitance: 0.1 uF  Voltage_Rating: 50V  [0603]  (hidden comment: CAPACITOR)
C35  Part_Number: 1000757  Capacitance: 0.1 uF  Voltage_Rating: 50V  [0603]  (hidden comment: CAPACITOR)
C36  Part_Number: 1000736  Capacitance: 1µF  [0402]  (hidden comment: C, 1 uF, 10V, 10%, X5R, 0402 CER)
C37  Part_Number: 1000742  Capacitance: 0.10µF  [0402]  (hidden comment: C, 0.1 uF, 16V, 10%, X7R, 0402 CER)
C38  Part_Number: 1000736  Capacitance: 1µF  [0402]  (hidden comment: C, 1 uF, 10V, 10%, X5R, 0402 CER)
C44  Capacitance: 22µF  Population: NP  [0603]  (hidden comment: 1000932)
C45  Part_Number: 1000742  Capacitance: 0.10µF  [0402]  (hidden comment: C, 0.1 uF, 16V, 10%, X7R, 0402 CER)
D4  Part_Number: 1000348  [D_LED_GREEN]  (hidden comment: LTST-C170GKT)
D5  Part_Number: 1000229  [DO-214AC, SMA]  (hidden comment: B340A-13-F)
D8  Part_Number: 1000185  [DO-214AC, SMA]  (hidden comment: SMAJ17A)
D11  Part_Number: 1000505  [SOT23-STYLE9]  (hidden comment: BAT54CLT1G)
FB1  Part_Number: 1002238  Resistance_at_Frequency: 120 ohm @ 100 MHz  [0603]  (hidden comment: FERRITE)
J15  Manufacturer_Part_Number1: PJ-002A  Part_Number: 1000221  [PJ-202A]  (hidden comment: PJ-202A)
J20  Population: NP  Part_Number: 1001255  [PRPC002SFAN-RC]  (hidden comment: PRPC002SFAN-RC)
L1  Manufacturer_Part_Number1: NRS5040T3R3NMGJV  Part_Number: 1002239  Inductance: 3.3uH  [NRS5040]  (hidden comment: INDUCTOR)
Q7  Manufacturer_Part_Number1: RUM001L02T2CL  Part_Number: 1001919  [SOT-723]  (hidden comment: MOSFET_N)
Q8  Manufacturer_Part_Number1: DMG2305UX-13  Part_Number: 1001920  [SOT95P300X115-3N]  (hidden comment: MOSFET_P)
R15  Part_Number: 1000796  Resistance_Ohms: 100k  [0402]  (hidden comment: R, 100K, 1%, 1/16W,  0402)
R16  Part_Number: 1000796  Resistance_Ohms: 100k  [0402]  (hidden comment: R, 100K, 1%, 1/16W,  0402)
R17  Part_Number: 1000796  Resistance_Ohms: 100k  [0402]  (hidden comment: R, 100K, 1%, 1/16W,  0402)
R18  Part_Number: 1000797  Resistance_Ohms: 1M  [0402]  (hidden comment: R, 1M, 1%, 1/16W, 0402)
R33  Resistance_Ohms: 715K  Part_Number: 1001436  [0402]  (hidden comment: Resistor, 715K, 1%, 1/10W, 0402)
R35  Part_Number: 1000796  Resistance_Ohms: 100k  [0402]  (hidden comment: R, 100K, 1%, 1/16W,  0402)
R36  Resistance_Ohms: 178K  Part_Number: 1001435  [0402]  (hidden comment: Resistor, 178K, 1%, 1/10W, 0402)
R37  Part_Number: 1000794  Resistance_Ohms: 1k  [0402]  (hidden comment: R, 1K, 1%, 1/16W, 0402)
SB31  Solder Bridge  [SOLDER BRIDGE 0603]  (value not drawn)  (no BOM)
SB32  Solder Bridge  [SOLDER BRIDGE 0603]  (value not drawn)  (no BOM)
SB33  Solder Bridge  [SOLDER BRIDGE 0603]  (value not drawn)  (no BOM)
SB42  Solder Bridge  [Solder Bridge 0603 Closed]  (value not drawn)
SB52  Solder Bridge  [SOLDER BRIDGE 0603]  (value not drawn)  (no BOM)
TP3  Test Point 1mm  [Test_Point 1mm]  (value not drawn)  (no BOM)
TP9  Test Point 1mm  [Test_Point 1mm]  (value not drawn)  (no BOM)
TP11  Test Point 1mm  [Test_Point 1mm]  (value not drawn)  (no BOM)
TP12  Test Point 1mm  [Test_Point 1mm]  (value not drawn)  (no BOM)
TP13  Test Point 1mm  [Test_Point 1mm]  (value not drawn)  (no BOM)
TP15  Test Point TH  [Keystone_5011]  (value not drawn)
TP20  Test Point 1mm  [Test_Point 1mm]  (value not drawn)  (no BOM)
U2  Part_Number: 1001908  [NCP114AMX180TCG]  (hidden comment: NCP114AMX180TCG)
U5  1001037  [QFN50P300X300X100_HS-17N]

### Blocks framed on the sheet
Skywire 4V Power: C7-C12 C34 C35 C44 D4 D5 D8 FB1 J15 J20 L1 Q7 R15 R16 R33 R35-R37 TP3 U5
1.8V reference power: C36-C38 R17 SB42 TP20 U2
SMT Power Test Points: TP9 TP11-TP13
TH Test Point: TP15

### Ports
PWR_nENABLE (in), PWR_PG (out), SKY_VREF_nENABLE (in)

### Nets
GND: C7.2 C8.2 C9.2 C10.2 C11.2 C12.2 C34.2 C35.2 C36.2 C37.2 C38.2 C44.2 C45.2 D8.A J15.3 J20.2 Q7.2(S) R16.1 R18.1 R36.1 R37.1 TP9.1 TP15.1 U2.2(GND) U2.5(PAD) U5.6(AGND) U5.8(DEF) U5.15(PGND_15) U5.16(PGND_16) U5.17(PAD)
VCC_1V8: C37.1 C38.1 SB31.1 TP11.1 U2.1(VOUT)
VCC_3V3_FTDI: D11.2 SB32.1
VCC_4V0: C9.1 C10.1 C11.1 C44.1 L1.2 R33.2 U5.7(FSW) U5.14(VOS)
VCC_ARD_3V3: SB42.1
VCC_ARD_IOREF: D11.1 SB33.1
VCC_SKY_VREF: Q8.3(D) SB52.2
VCC_VIN: C7.1 C34.1 D4.1(Anode) D5.K FB1.1 TP12.1
VCC_VREF: C45.1 D11.3 Q8.2(S) R35.2 SB31.2 SB32.2 SB33.2 SB52.1 TP13.1
PWR_nENABLE: Q7.1(G) R16.2 ; port PWR_nENABLE
NetC8_1: C8.1 C35.1 FB1.2 R15.2 U5.10(AVIN) U5.11(PVIN_11) U5.12(PVIN_12)
NetC12_1: C12.1 U5.9(SS/TR)
NetC36_1: C36.1 R17.2 SB42.2 U2.4(VIN)
NetD4_2: D4.2(Cathode) R37.2
NetD5_A: D5.A D8.K J15.1 J20.1
NetL1_1: L1.1 U5.1(SW_1) U5.2(SW_2) U5.3(SW_3)
NetQ7_3: Q7.3(D) R15.1 TP3.1 U5.13(EN)
NetQ8_1: Q8.1(G) R18.2 ; port SKY_VREF_nENABLE
NetR17_1: R17.1 TP20.1 U2.3(EN)
NetR33_1: R33.1 R36.2 U5.5(FB)
NetR35_1: R35.1 U5.4(PG) ; port PWR_PG

Not connected (* = marked no-connect by the designer): J15 2*

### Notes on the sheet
- Power
- DESIGN NOTE:
  U5 output voltage (VCC_4V0) set to 4.01V.
  Vout=0.8V*(1+(R33/R36))=4.01V
- (near J15) DESIGN NOTE:
  12V input voltage.
- DESIGN NOTE:
  There may be some leakage current due to slight voltage missmatch from D11 Vf. Populate  SB32 or SB33 for low power testing if needed.
- Skywire VREF Power
- DESIGN NOTE:
  Do not plug in the development kits USB ports when using the Skywire Development kit with a 1.8V Arduino IO referenced development kit as the Skywire IO will be set to 3.3V.
- © NimbeLink Corp. 2020. All rights reserved.

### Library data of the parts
C7 C8 = 1000780: Capacitor, 10 uF, 25V, 10%, X5R, 0805; Manufacturer1: Samsung Electro-Mechanics America, Inc; Manufacturer_Part_Number1: CL21A106KAYNNNE; Item_Phase: Production; Capacitor_Type: Ceramic; Mounting_Type: Surface Mount; Operating_Temperature: -55°C ~ 85°C; Thickness_Max: 0.057" (1.45mm)
C9 C44 = 1000932: Capacitor, 22 uF, 25V, 20%, X5R, 0603; Manufacturer1: TDK Corporation; Manufacturer_Part_Number1: C1608X5R1A226M080AC; Item_Phase: Production; Capacitor_Type: Ceramic; Mounting_Type: Surface Mount; Operating_Temperature: -55°C ~ 85°C; Thickness_Max: 0.035" (0.90mm); Voltage_Rating: 10V
C10 C11 C37 C45 = 1000742: Capacitor, 0.1 uF, 16V, 10%, X7R, 0402; Manufacturer1: Samsung Electro-Mechanics America, Inc; Manufacturer_Part_Number1: CL05B104KO5NNNC; Item_Phase: Production; Capacitor_Type: Ceramic; Mounting_Type: Surface Mount; Operating_Temperature: -55°C ~ 125°C; Thickness_Max: 0.022" (0.55mm)
C12 = 1001496: Capacitor, 270 pF, 50V, 5%, C0G/NPO, 0402; Manufacturer1: Taiyo Yuden; Manufacturer_Part_Number1: UMK105CG271JV-F; Item_Phase: Production; Capacitor_Type: Ceramic; Mounting_Type: Surface Mount; Operating_Temperature: -55°C ~ 125°C; Temperature_Coefficient: C0G, NP0; Thickness_Max: 0.022" (0.55mm)
C34 C35 = 1000757: as C31 on sheet TOP
C36 C38 = 1000736: Capacitor, 1 uF, 10V, 10%, X5R, 0402; Manufacturer1: AVX Corporation; Manufacturer_Part_Number1: 0402ZD105KAT4A; Item_Phase: Production; Capacitor_Type: Ceramic; Mounting_Type: Surface Mount; Operating_Temperature: -55°C ~ 85°C; Thickness_Max: 0.022" (0.55mm)
D4 = 1000348: as D3 on sheet TOP
D5 = 1000229: Diode, Schottky, 40V, 0.500 Vf, 3A, SMA; Manufacturer1: Diodes Incorporated; Item_Phase: Production; Current_Reverse_Leakage_at_Vref: 500µA @ 40V; Mounting_Type: Surface Mount; Operating_Temperature: -55°C ~ 150°C; Voltage_Forward_VF_Max_at_I_Forward: 500mV @ 3A
D8 = 1000185: Diode, TVS, Unidirectional, 17V, 14.5A, SMA; Manufacturer1: Bourns Inc; Item_Phase: Production; Diode_Type: Zener; Mounting_Type: Surface Mount; Operating_Temperature: -55°C ~ 150°C (TJ)
D11 = 1000505: as D6 on sheet TOP
FB1 = 1002238: as FB3 on sheet TOP
J15 = 1000221: Connector, Barrel, 24V, 2.5A, 2.1mm ID, 5.5mm OD; Manufacturer1: CUI Inc; Item_Phase: Production; Connector_Type: Jack; Contact_Type: Male Pin; Gender: Male; Header_Orientation: Horizontal; Insertion_Removal_Method: Push In / Pull Out; Mounting_Type: Through Hole; Operating_Temperature: -25°C ~ 85°C; Voltage_Rating: 24VDC
J20 = 1001255: Connector, Header, Male, 2.54mm, 2x1, TH; Manufacturer1: Sullins Connector Solutions; Item_Phase: Production; Connector_Type: Header, Unshrouded, Breakaway; Contact_Finish: Gold; Contact_Type: Male Pin; Mounting_Type: Through Hole; Number_of_Pins: 2; Number_of_Rows: 1; Pitch: 0.100 (2.54mm)"
L1 = 1002239: Inductor, 3.3 uH, 3.3A, 30%, 35.1 mOhm, Shielded, 4.90x4.90x2.00mm; Manufacturer1: Taiyo Yuden; Item_Phase: Production; Current_Saturation: 4A; Frequency_Self_Resonant: 32MHz; Mounting_Type: Surface Mount; Operating_Temperature: -40C to 125C; Inductor_Type: Wirewound
Q7 = 1001919: Transistor, MOSFET, N-CH, 20V, 0.100A, SOT-723; Manufacturer1: Rohm Semiconductor; Item_Phase: Production; Current_Continuous_Drain_at_25_deg_C: 100mA; Mounting_Type: Surface Mount; Operating_Temperature: -55 to 150C; Power_Max: 150 mW; Transistor_Type: NCH - FET
Q8 = 1001920: Transistor, MOSFET, P-CH, 20V, 4.2A, SOT-23-3; Manufacturer1: Diodes Incorporated; Item_Phase: Production; Mounting_Type: Surface Mount; Operating_Temperature: -55 to 150C; Power_Max: 1.4W; Transistor_Type: PCH - FET
R15-R17 R35 = 1000796: as R24 on sheet TOP
R18 = 1000797: Resistor, 1M, 1%, 1/16W, 0402; Manufacturer1: Bourns Inc; Manufacturer_Part_Number1: CR0402-FX-1004GLF; Item_Phase: Production; Mounting_Type: Surface Mount; Number_of_Terminations: 2; Operating_Temperature: -55°C ~ 155°C; Power: 0.063W, 1/16W; Resistor_Package: 0402 (1005 Metric); Temperature_Coefficient: ±100ppm/°C
R33 = 1001436: Manufacturer1: Panasonic Electronic Components; Manufacturer_Part_Number1: ERJ-2RKF7153X; Item_Phase: Production; Mounting_Type: Surface Mount; Number_of_Terminations: 2; Resistor_Package: 0402 (1005 Metric)
R36 = 1001435: Manufacturer1: Panasonic Electronic Components; Manufacturer_Part_Number1: ERJ-2RKF1783X; Item_Phase: Production; Mounting_Type: Surface Mount; Resistor_Package: 0402 (1005 Metric)
R37 = 1000794: Resistor, 1K, 1%, 1/16W, 0402; Manufacturer1: Bourns Inc; Manufacturer_Part_Number1: CR0402-FX-1001GLF; Item_Phase: Production; Mounting_Type: Surface Mount; Number_of_Terminations: 2; Operating_Temperature: -55°C ~ 155°C; Power: 0.063W, 1/16W; Resistor_Package: 0402 (1005 Metric); Temperature_Coefficient: ±100ppm/°C
SB31-SB33 SB52 = Solder Bridge, Open: Population: NP
SB42 = 1002269: as SB1 on sheet TOP
TP3 TP9 TP11-TP13 TP20 = TP_1mm: TEST POINT, SMD 1mm; Population: NP
TP15 = 1002259: Connector, PC Test Point, 1 pin, Black, Silver Plate, TH, 3.17mmx11.30mm; Manufacturer_Part_Number1: 5011; Manufacturer1: Keystone Electronics; Item_Phase: Preliminary; Contact_Type: Male Pin; Gender: Male; Header_Orientation: Vertical; Height_Above_Board: 8.13mm; Mounting_Type: Through Hole; Number_of_Pins: 1
U2 = 1001908: IC, LDO, 1.8V, 300mA, 4-UDFN, 1.0x1.0mm; Manufacturer1: ON Semiconductor; Item_Phase: Preliminary; Mounting_Type: Surface Mount; Operating_Temperature: -40C to 85C; Voltage_Supply_Max: 5.5 V; Voltage_Supply_Min: 1.7V
U5 = 1001037: IC, Buck, ADJ, 3V-17V , 2A, QFN; Manufacturer1: Texas Instruments; Item_Phase: Production; Mounting_Type: Surface Mount; Operating_Temperature: -40°C ~ 85°C; Output_Type: Adjustable

## Sheet Skywire.SchDoc: SKYWIRE
size C; DocumentNumber: 3; SheetNumber: 3; SheetTotal: 6
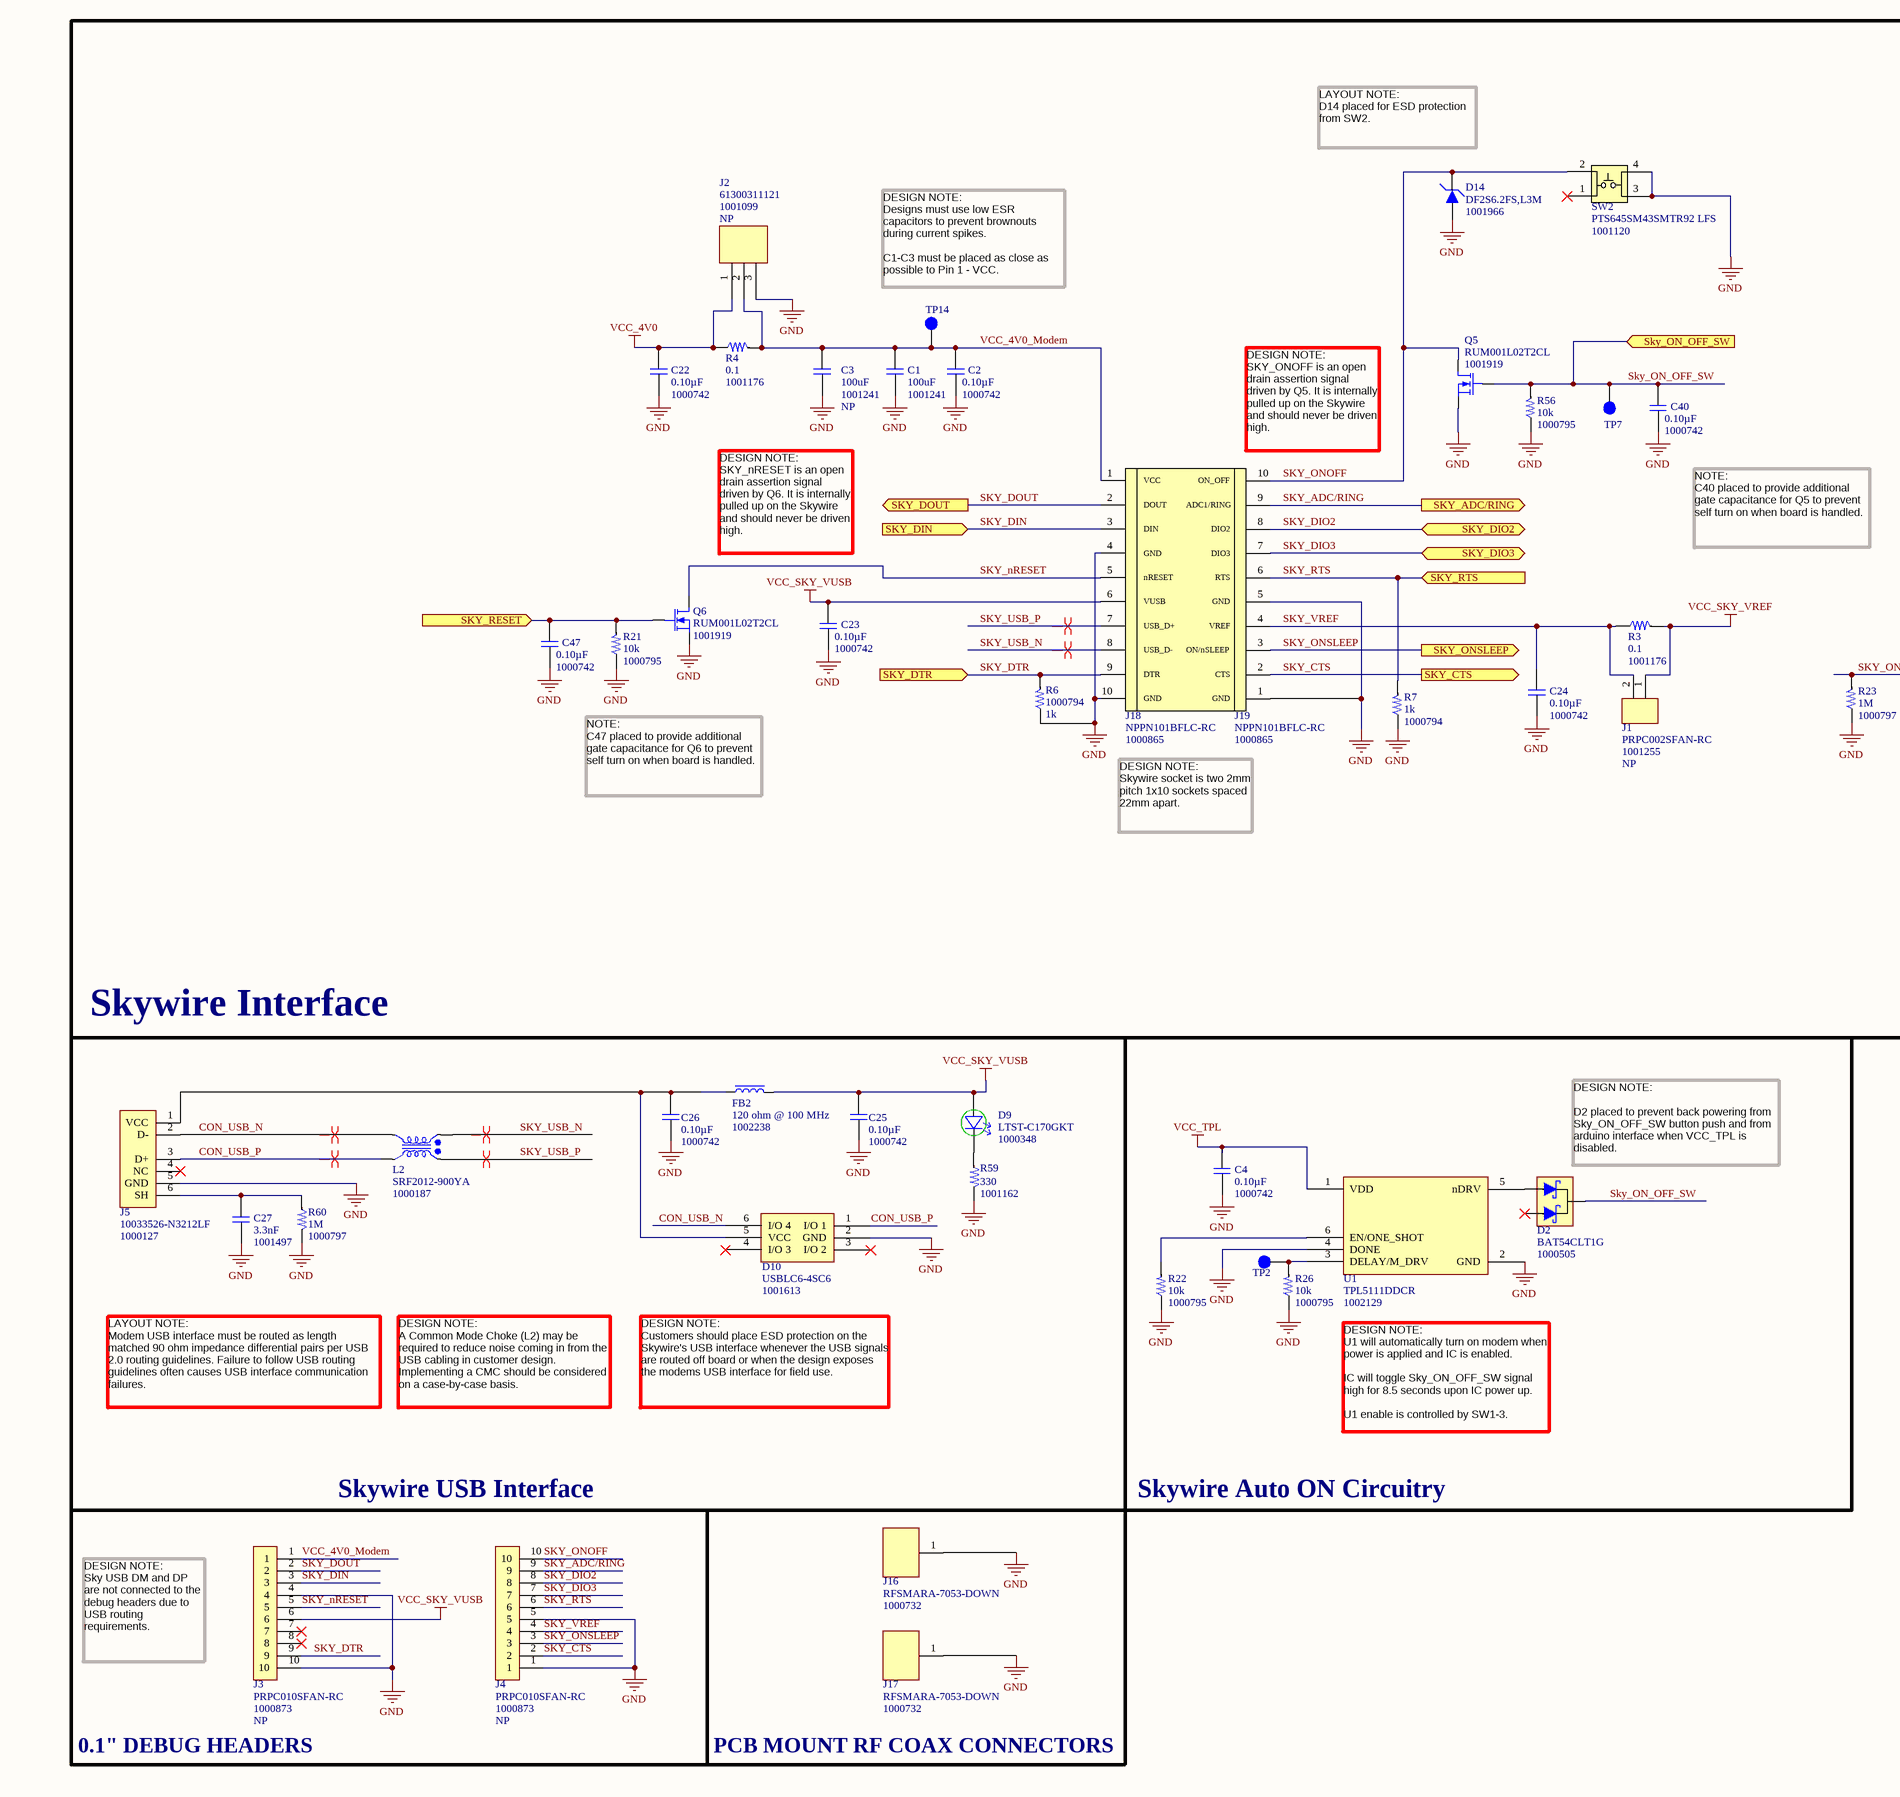
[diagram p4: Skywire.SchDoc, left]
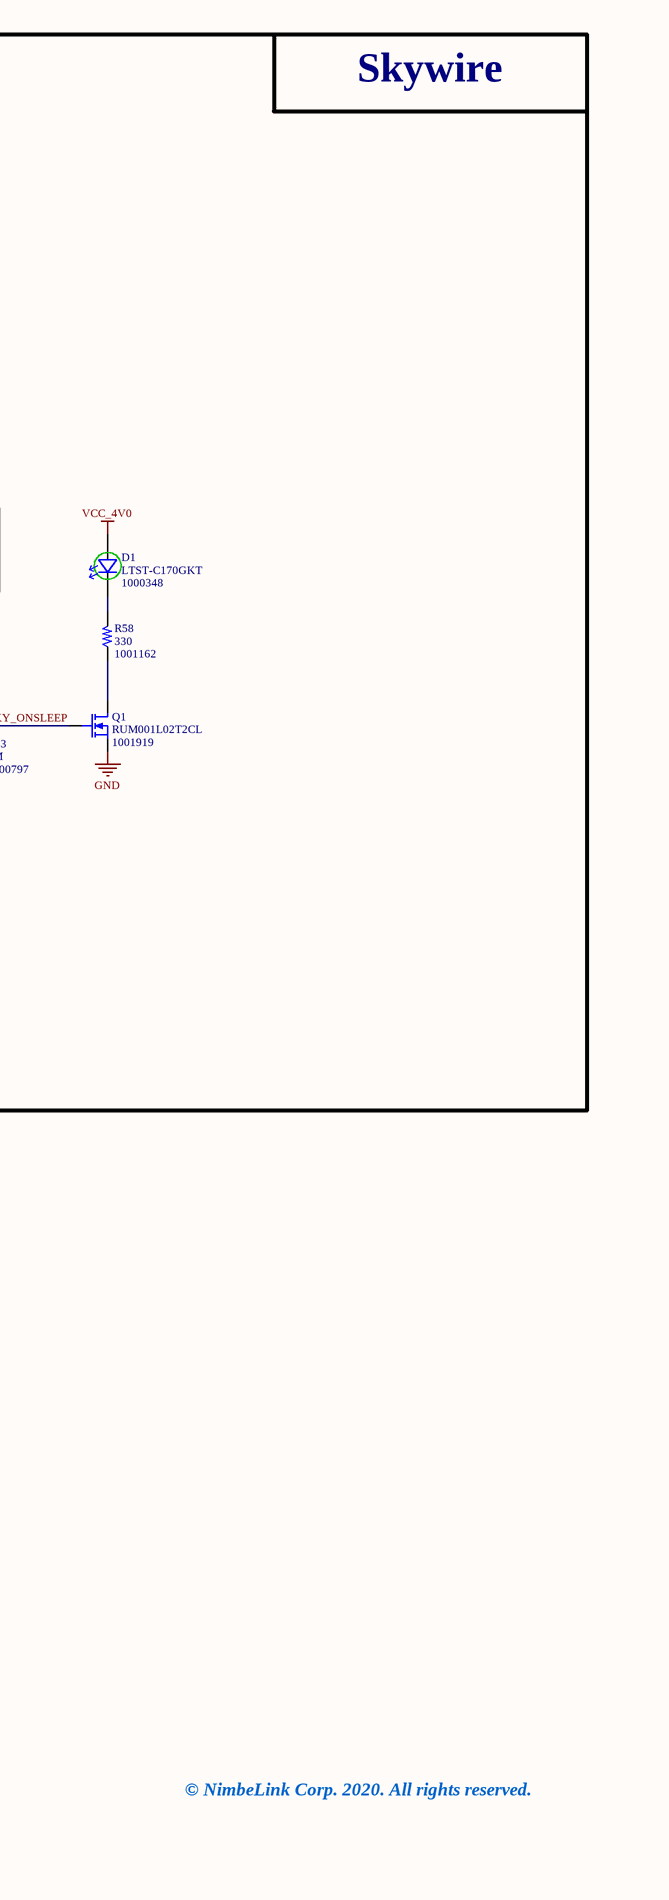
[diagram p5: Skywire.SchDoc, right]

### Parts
C1  Capacitance: 100uF  [CAPC3225X25N_1210]  (hidden comment: 1001241)
C2  Capacitance: 0.10µF  Part_Number: 1000742  [0402]
C3  Population: NP  Capacitance: 100uF  [CAPC3225X25N_1210]  (hidden comment: 1001241)
C4  Capacitance: 0.10µF  Part_Number: 1000742  [0402]
C22  Capacitance: 0.10µF  Part_Number: 1000742  [0402]
C23  Capacitance: 0.10µF  Part_Number: 1000742  [0402]
C24  Capacitance: 0.10µF  Part_Number: 1000742  [0402]
C25  Capacitance: 0.10µF  Part_Number: 1000742  [0402]
C26  Capacitance: 0.10µF  Part_Number: 1000742  [0402]
C27  Part_Number: 1001497  Capacitance: 3.3nF  [0402]  (hidden comment: CAPACITOR)
C40  Capacitance: 0.10µF  Part_Number: 1000742  [0402]
C47  Capacitance: 0.10µF  Part_Number: 1000742  [0402]
D1  Part_Number: 1000348  [D_LED_GREEN]  (hidden comment: LTST-C170GKT)
D2  Part_Number: 1000505  [SOT23-STYLE9]  (hidden comment: BAT54CLT1G)
D9  Part_Number: 1000348  [D_LED_GREEN]  (hidden comment: LTST-C170GKT)
D10  Part_Number: 1001613  [SOT23-6L]  (hidden comment: USBLC6-4SC6)
D14  Manufacturer_Part_Number1: DF2S6.2FS,L3M  Part_Number: 1001966  [SOD-923]  (hidden comment: TVS)
FB2  Part_Number: 1002238  Resistance_at_Frequency: 120 ohm @ 100 MHz  [0603]  (hidden comment: FERRITE)
J1  Population: NP  Part_Number: 1001255  [PRPC002SFAN-RC]  (hidden comment: PRPC002SFAN-RC)
J2  Population: NP  Part_Number: 1001099  [61300311121]  (hidden comment: 61300311121)
J3  Population: NP  Part_Number: 1000873  [PRPC010SFAN-RC]  (hidden comment: PRPC010SFAN-RC)
J4  Population: NP  Part_Number: 1000873  [PRPC010SFAN-RC]  (hidden comment: PRPC010SFAN-RC)
J5  Part_Number: 1000127  [10033526-N3212LF]  (hidden comment: USB MINI B)
J16  Part_Number: 1000732  [UFL TO SMA]  (hidden comment: UFL to SMA)
J17  Part_Number: 1000732  [UFL TO SMA]  (hidden comment: UFL to SMA)
J18  1000865  [NPPN101BFLC-RC]
J19  1000865  [NPPN101BFLC-RC]
L2  Part_Number: 1000187  [SRF2012-900YA]  (hidden comment: SRF2012-900YA)
Q1  Manufacturer_Part_Number1: RUM001L02T2CL  Part_Number: 1001919  [SOT-723]  (hidden comment: MOSFET_N)
Q5  Manufacturer_Part_Number1: RUM001L02T2CL  Part_Number: 1001919  [SOT-723]  (hidden comment: MOSFET_N)
Q6  Manufacturer_Part_Number1: RUM001L02T2CL  Part_Number: 1001919  [SOT-723]  (hidden comment: MOSFET_N)
R3  Part_Number: 1001176  Resistance_Ohms: 0.1  [0603]  (hidden comment: R, 0.1, 1%, 1/4W, 0603)
R4  Part_Number: 1001176  Resistance_Ohms: 0.1  [0603]  (hidden comment: R, 0.1, 1%, 1/4W, 0603)
R6  Part_Number: 1000794  Resistance_Ohms: 1k  [0402]  (hidden comment: R, 1K, 1%, 1/16W, 0402)
R7  Part_Number: 1000794  Resistance_Ohms: 1k  [0402]  (hidden comment: R, 1K, 1%, 1/16W, 0402)
R21  Part_Number: 1000795  Resistance_Ohms: 10k  [0402]  (hidden comment: R, 10K, 1%, 1/16W,  0402)
R22  Part_Number: 1000795  Resistance_Ohms: 10k  [0402]  (hidden comment: R, 10K, 1%, 1/16W,  0402)
R23  Part_Number: 1000797  Resistance_Ohms: 1M  [0402]  (hidden comment: R, 1M, 1%, 1/16W, 0402)
R26  Part_Number: 1000795  Resistance_Ohms: 10k  [0402]  (hidden comment: R, 10K, 1%, 1/16W,  0402)
R56  Part_Number: 1000795  Resistance_Ohms: 10k  [0402]  (hidden comment: R, 10K, 1%, 1/16W,  0402)
R58  Part_Number: 1001162  Resistance_Ohms: 330  [0402]  (hidden comment: R, 330, 1%, 1/10W, 0402)
R59  Part_Number: 1001162  Resistance_Ohms: 330  [0402]  (hidden comment: R, 330, 1%, 1/10W, 0402)
R60  Part_Number: 1000797  Resistance_Ohms: 1M  [0402]  (hidden comment: R, 1M, 1%, 1/16W, 0402)
SW2  Part_Number: 1001120  [PTS645SM43SMTR92 LFS]  (hidden comment: PTS645SM43SMTR92 LFS)
TP2  Test Point 1mm  [Test_Point 1mm]  (value not drawn)  (no BOM)
TP7  Test Point 1mm  [Test_Point 1mm]  (value not drawn)  (no BOM)
TP14  Test Point 1mm  [Test_Point 1mm]  (value not drawn)  (no BOM)
U1  Manufacturer_Part_Number1: TPL5111DDCR  Part_Number: 1002129  [SOT95P280X110-6N]  (hidden comment: TPL5111)

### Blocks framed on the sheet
Skywire: C1-C3 C22-C24 C40 C47 D1 D14 J1 J2 J18 J19 Q1 Q5 Q6 R3 R4 R6 R7 R21 R23 R56 R58 SW2 TP7 TP14
Skywire Interface: C25-C27 D9 D10 FB2 J5 L2 R59 R60
Skywire Auto ON Circuitry: C4 D2 R22 R26 TP2 U1
Skywire USB Interface: J3 J4
PCB MOUNT RF COAX CONNECTORS: J16 J17

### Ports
SKY_ADC/RING (out), SKY_CTS (out), SKY_DIN (in), SKY_DIO2 (bidir), SKY_DIO3 (bidir), SKY_DOUT (out), SKY_DTR (in), Sky_ON_OFF_SW (in), SKY_ONSLEEP (out), SKY_RESET (in), SKY_RTS (in)

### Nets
GND: C1.2 C2.2 C3.2 C4.2 C22.2 C23.2 C24.2 C25.2 C26.2 C27.1 C40.2 C47.2 D10.2(GND) D14.A J2.3 J3.4 J3.10 J4.1 J4.5 J5.5(GND) J16.1 J17.1 J18.4 J18.10 J19.1 J19.5 Q1.2(S) Q5.2(S) Q6.2(S) R6.1 R7.1 R21.1 R22.1 R23.1 R26.1 R56.1 R59.1 R60.1 SW2.3 SW2.4 U1.2(GND) U1.4(DONE)
VCC_4V0: C22.1 D1.1(Anode) J2.1 R4.1
VCC_SKY_VREF: J1.1 R3.2
VCC_SKY_VUSB: C23.1 C25.1 D9.1(Anode) FB2.1 J3.6 J18.6
VCC_TPL: C4.1 U1.1(VDD)
CON_USB_N: D10.6(I/O_4) J5.2(D-) L2.3
CON_USB_P: D10.1(I/O_1) J5.3(D+) L2.4
SKY_ADC/RING: J4.9 J19.9 ; port SKY_ADC/RING
SKY_CTS: J4.2 J19.2 ; port SKY_CTS
SKY_DIN: J3.3 J18.3 ; port SKY_DIN
SKY_DIO2: J4.8 J19.8 ; port SKY_DIO2
SKY_DIO3: J4.7 J19.7 ; port SKY_DIO3
SKY_DOUT: J3.2 J18.2 ; port SKY_DOUT
SKY_DTR: J3.9 J18.9 R6.2 ; port SKY_DTR
SKY_nRESET: J3.5 J18.5 Q6.3(D)
Sky_ON_OFF_SW: C40.1 D2.3 Q5.1(G) R56.2 TP7.1 ; port Sky_ON_OFF_SW
SKY_ONOFF: D14.K J4.10 J19.10 Q5.3(D) SW2.2
SKY_ONSLEEP: J4.3 J19.3 Q1.1(G) R23.2 ; port SKY_ONSLEEP
SKY_RTS: J4.6 J19.6 R7.2 ; port SKY_RTS
SKY_USB_N: J18.8 L2.2
SKY_USB_P: J18.7 L2.1
SKY_VREF: C24.1 J1.2 J4.4 J19.4 R3.1
VCC_4V0_Modem: C1.1 C2.1 C3.1 J2.2 J3.1 J18.1 R4.2 TP14.1
NetC26_1: C26.1 D10.5(VCC) FB2.2 J5.1(VCC)
NetC27_2: C27.2 J5.6(SH) R60.2
NetC47_1: C47.1 Q6.1(G) R21.2 ; port SKY_RESET
NetD1_2: D1.2(Cathode) R58.2
NetD2_1: D2.1 U1.5(nDRV)
NetD9_2: D9.2(Cathode) R59.2
NetQ1_3: Q1.3(D) R58.1
NetR22_2: R22.2 U1.6(EN/ONE_SHOT)
NetR26_2: R26.2 TP2.1 U1.3(DELAY/M_DRV)

Not connected (* = marked no-connect by the designer): D2 2*; D10 3(I/O_2)* 4(I/O_3)*; J3 7* 8*; J5 4(NC)*; SW2 1*

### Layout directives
differential pair; net class DIFF90: CON_USB_N, CON_USB_P, SKY_USB_N, SKY_USB_P
differential pair: SKY_USB_N, SKY_USB_P

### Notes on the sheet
- (near D14) LAYOUT NOTE:
  D14 placed for ESD protection from SW2.
- (near TP14) DESIGN NOTE:
  Designs must use low ESR capacitors to prevent brownouts during current spikes.
  C1-C3 must be placed as close as possible to Pin 1 - VCC.
- (near J18) VCC
- (near J19) ON_OFF
- (near J19) DESIGN NOTE:
  SKY_ONOFF is an open drain assertion signal driven by Q5. It is internally pulled up on the Skywire and should never be driven high.
- DESIGN NOTE:
  SKY_nRESET is an open drain assertion signal driven by Q6. It is internally pulled up on the Skywire and should never be driven high.
- (near J18) DOUT
- (near J18) DIN
- (near J19) ADC1/RING
- (near J19) DIO2
- NOTE:
  C40 placed to provide additional gate capacitance for Q5 to prevent self turn on when board is handled.
- (near J18) GND
- (near J18) nRESET
- (near J18) VUSB
- (near J19) DIO3
- (near J19) GND
- (near J19) RTS
- (near J18) USB_D+
- (near J18) USB_D-
- (near J19) ON/nSLEEP
- (near J19) VREF
- (near J18) DTR
- (near J19) CTS
- NOTE:
  C47 placed to provide additional gate capacitance for Q6 to prevent self turn on when board is handled.
- DESIGN NOTE:
  Skywire socket is two 2mm pitch 1x10 sockets spaced 22mm apart.
- (near D2) DESIGN NOTE:
  D2 placed to prevent back powering from Sky_ON_OFF_SW button push and from arduino interface when VCC_TPL is disabled.
- LAYOUT NOTE:
  Modem USB interface must be routed as length matched 90 ohm impedance differential pairs per USB 2.0 routing guidelines. Failure to follow USB routing guidelines often causes USB interface communication failures.
- DESIGN NOTE:
  A Common Mode Choke (L2) may be required to reduce noise coming in from the USB cabling in customer design. Implementing a CMC should be considered on a case-by-case basis.
- DESIGN NOTE:
  Customers should place ESD protection on the Skywire's USB interface whenever the USB signals are routed off board or when the design exposes the modems USB interface for field use.
- DESIGN NOTE:
  U1 will automatically turn on modem when power is applied and IC is enabled.
  IC will toggle Sky_ON_OFF_SW signal high for 8.5 seconds upon IC power up.
  U1 enable is controlled by SW1-3.
- DESIGN NOTE:
  Sky USB DM and DP are not connected to the debug headers due to USB routing requirements.
- © NimbeLink Corp. 2020. All rights reserved.
- 0.1" DEBUG HEADERS

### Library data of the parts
C1 C3 = 1001241: Capacitor. 100uF, 10V, 20%, X5R, 1210; Manufacturer1: Taiyo Yuden; Tolerance: +/- 20%; Item_Phase: Production; Capacitor_Type: Ceramic; Mounting_Type: Surface Mount; Operating_Temperature: -55C ~ +85C; Thickness_Max: 0.106 (2.70mm)"
C2 C4 C22-C26 C40 C47 = 1000742: as C5 on sheet TOP
C27 = 1001497: as C15 on sheet TOP
D1 D9 = 1000348: as D3 on sheet TOP
D2 = 1000505: as D6 on sheet TOP
D10 = 1001613: Diode, TVS, USB, ESD, Unidirectional, 5.25V, 5A, 4CH, SOT23-6; Manufacturer1: STMicroelectronics; Item_Phase: Production; Capacitance_at_Frequency: 3pF@1MHz; Current_Reverse_Leakage_at_Vref: 10nA; Mounting_Type: Surface Mount; Operating_Temperature: -40 to +125C
D14 = 1001966: Diode, TVS, Unidirectional, 5V, SOD-923; Manufacturer1: Toshiba Semiconductor and Storage; Item_Phase: Production; Capacitance_at_Frequency: 32pF @ 1MHz; Current_Reverse_Leakage_at_Vref: 2.5uA; Mounting_Type: Surface Mount; Voltage_DC_Reverse_VR_Max: 5
FB2 = 1002238: as FB3 on sheet TOP
J1 = 1001255: as J20 on sheet Power
J2 = 1001099: Connector, Header, Male, 2.54mm, 3x1, TH; Manufacturer1: Wurth Electronics Inc; Item_Phase: Production; Connector_Type: Header, Unshrouded; Contact_Finish: Gold; Contact_Type: Male Pin; Mounting_Type: Through Hole; Number_of_Positions: 3; Number_of_Positions_Loaded: All; Number_of_Rows: 1; Pitch: 0.100" (2.54mm)
J3 J4 = 1000873: as J10 on sheet TOP
J5 = 1000127: as J14 on sheet TOP
J16 J17 = 1000732: Connector, ANT, UFL to PCB Mount SMA, UFL Down, 53mm, TH; Manufacturer1: ROHO COMMUNICATION TECHNOLOGY CO. Ltd; Item_Phase: Production; Connector_Type: Female U.Fl to PCB Mount Female SMA Antenna Cable; Contact_Type: Female Socket; Gender: Female; Header_Orientation: Horizontal; Impedance: 50 Ohm; Mounting_Type: Other
J18 J19 = 1000865: Connector, Female, 2.00mm, 10x1, SMD, Left Oriented; Manufacturer1: Sullins Connector Solutions; Item_Phase: Production; Connector_Type: Header; Contact_Finish: Gold; Contact_Type: Female Socket; Current_Rating: 2A; Fastening_Type: Push-Pull; Header_Orientation: Vertical; Insertion_Removal_Method: Push In / Pull Out; Mounting_Type: Surface Mount; Number_of_Pins: 10; Number_of_Rows: 1; Operating_Temperature: -40°C ~ 105°C; Pitch: 0.079" (2.00mm); Voltage_Rating: 150V
L2 = 1000187: Common Mode Choke, 0.400A, 90Ohm, 300mOhm-DC, 2LN, SMD; Part_Type: Ferrite; Manufacturer1: Bourns Inc; Resistance_at_Frequency: 90 Ohm @ 100MHz; Item_Phase: Production; Mounting_Type: Surface Mount; Operating_Temperature: -40°C ~ 125°C; Resistance_DC: 300 mOhm Max
Q1 Q5 Q6 = 1001919: as Q7 on sheet Power
R3 R4 = 1001176: Resistor, 0.1, 1%, 1/4W, 0603; Manufacturer1: Panasonic Electronic Components; Manufacturer_Part_Number1: ERJ-L06KF10CV; Item_Phase: Production; Mounting_Type: Surface Mount; Number_of_Terminations: 2; Operating_Temperature: -55°C ~ 125°C; Power: 0.25W, 1/4W; Resistor_Package: 0805 (2012 Metric); Temperature_Coefficient: ±100ppm/°C
R6 R7 = 1000794: as R37 on sheet Power
R21 R22 R26 R56 = 1000795: as R11 on sheet TOP
R23 = 1000797: as R18 on sheet Power
R58 R59 = 1001162: as R1 on sheet TOP
R60 = 1000797: as R2 on sheet TOP
SW2 = 1001120: Switch, SPST-NO, 12V, 0.05A, 6.00x6.00mm, SMD; Manufacturer1: C&K Components; Item_Phase: Production; Actuator_Type: Button; Contact_Current_Rating_at_Voltage: 0.05A @ 12VDC; Mechanical_Life: 100,000 Cycles; Mounting_Type: Surface Mount; Operating_Force: 160gf; Operating_Temperature: -20°C ~ 60°C
TP2 TP7 TP14 = TP_1mm: TEST POINT, SMD 1mm; Population: NP
U1 = 1002129: IC, Timer, 0.1-7200s, 1%, 1.8V-5.5V, TSOT-23-6; Manufacturer1: Texas Instruments; Item_Phase: Production; IC_Function: Logic; Mounting_Type: Surface Mount; Operating_Temperature: -40C to +105C; Voltage_Supply_Max: 5.5V; Voltage_Supply_Min: 1.8V; Voltage_Supply_Typical: 3.3V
